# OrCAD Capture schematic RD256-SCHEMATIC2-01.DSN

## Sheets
1 10: size A3
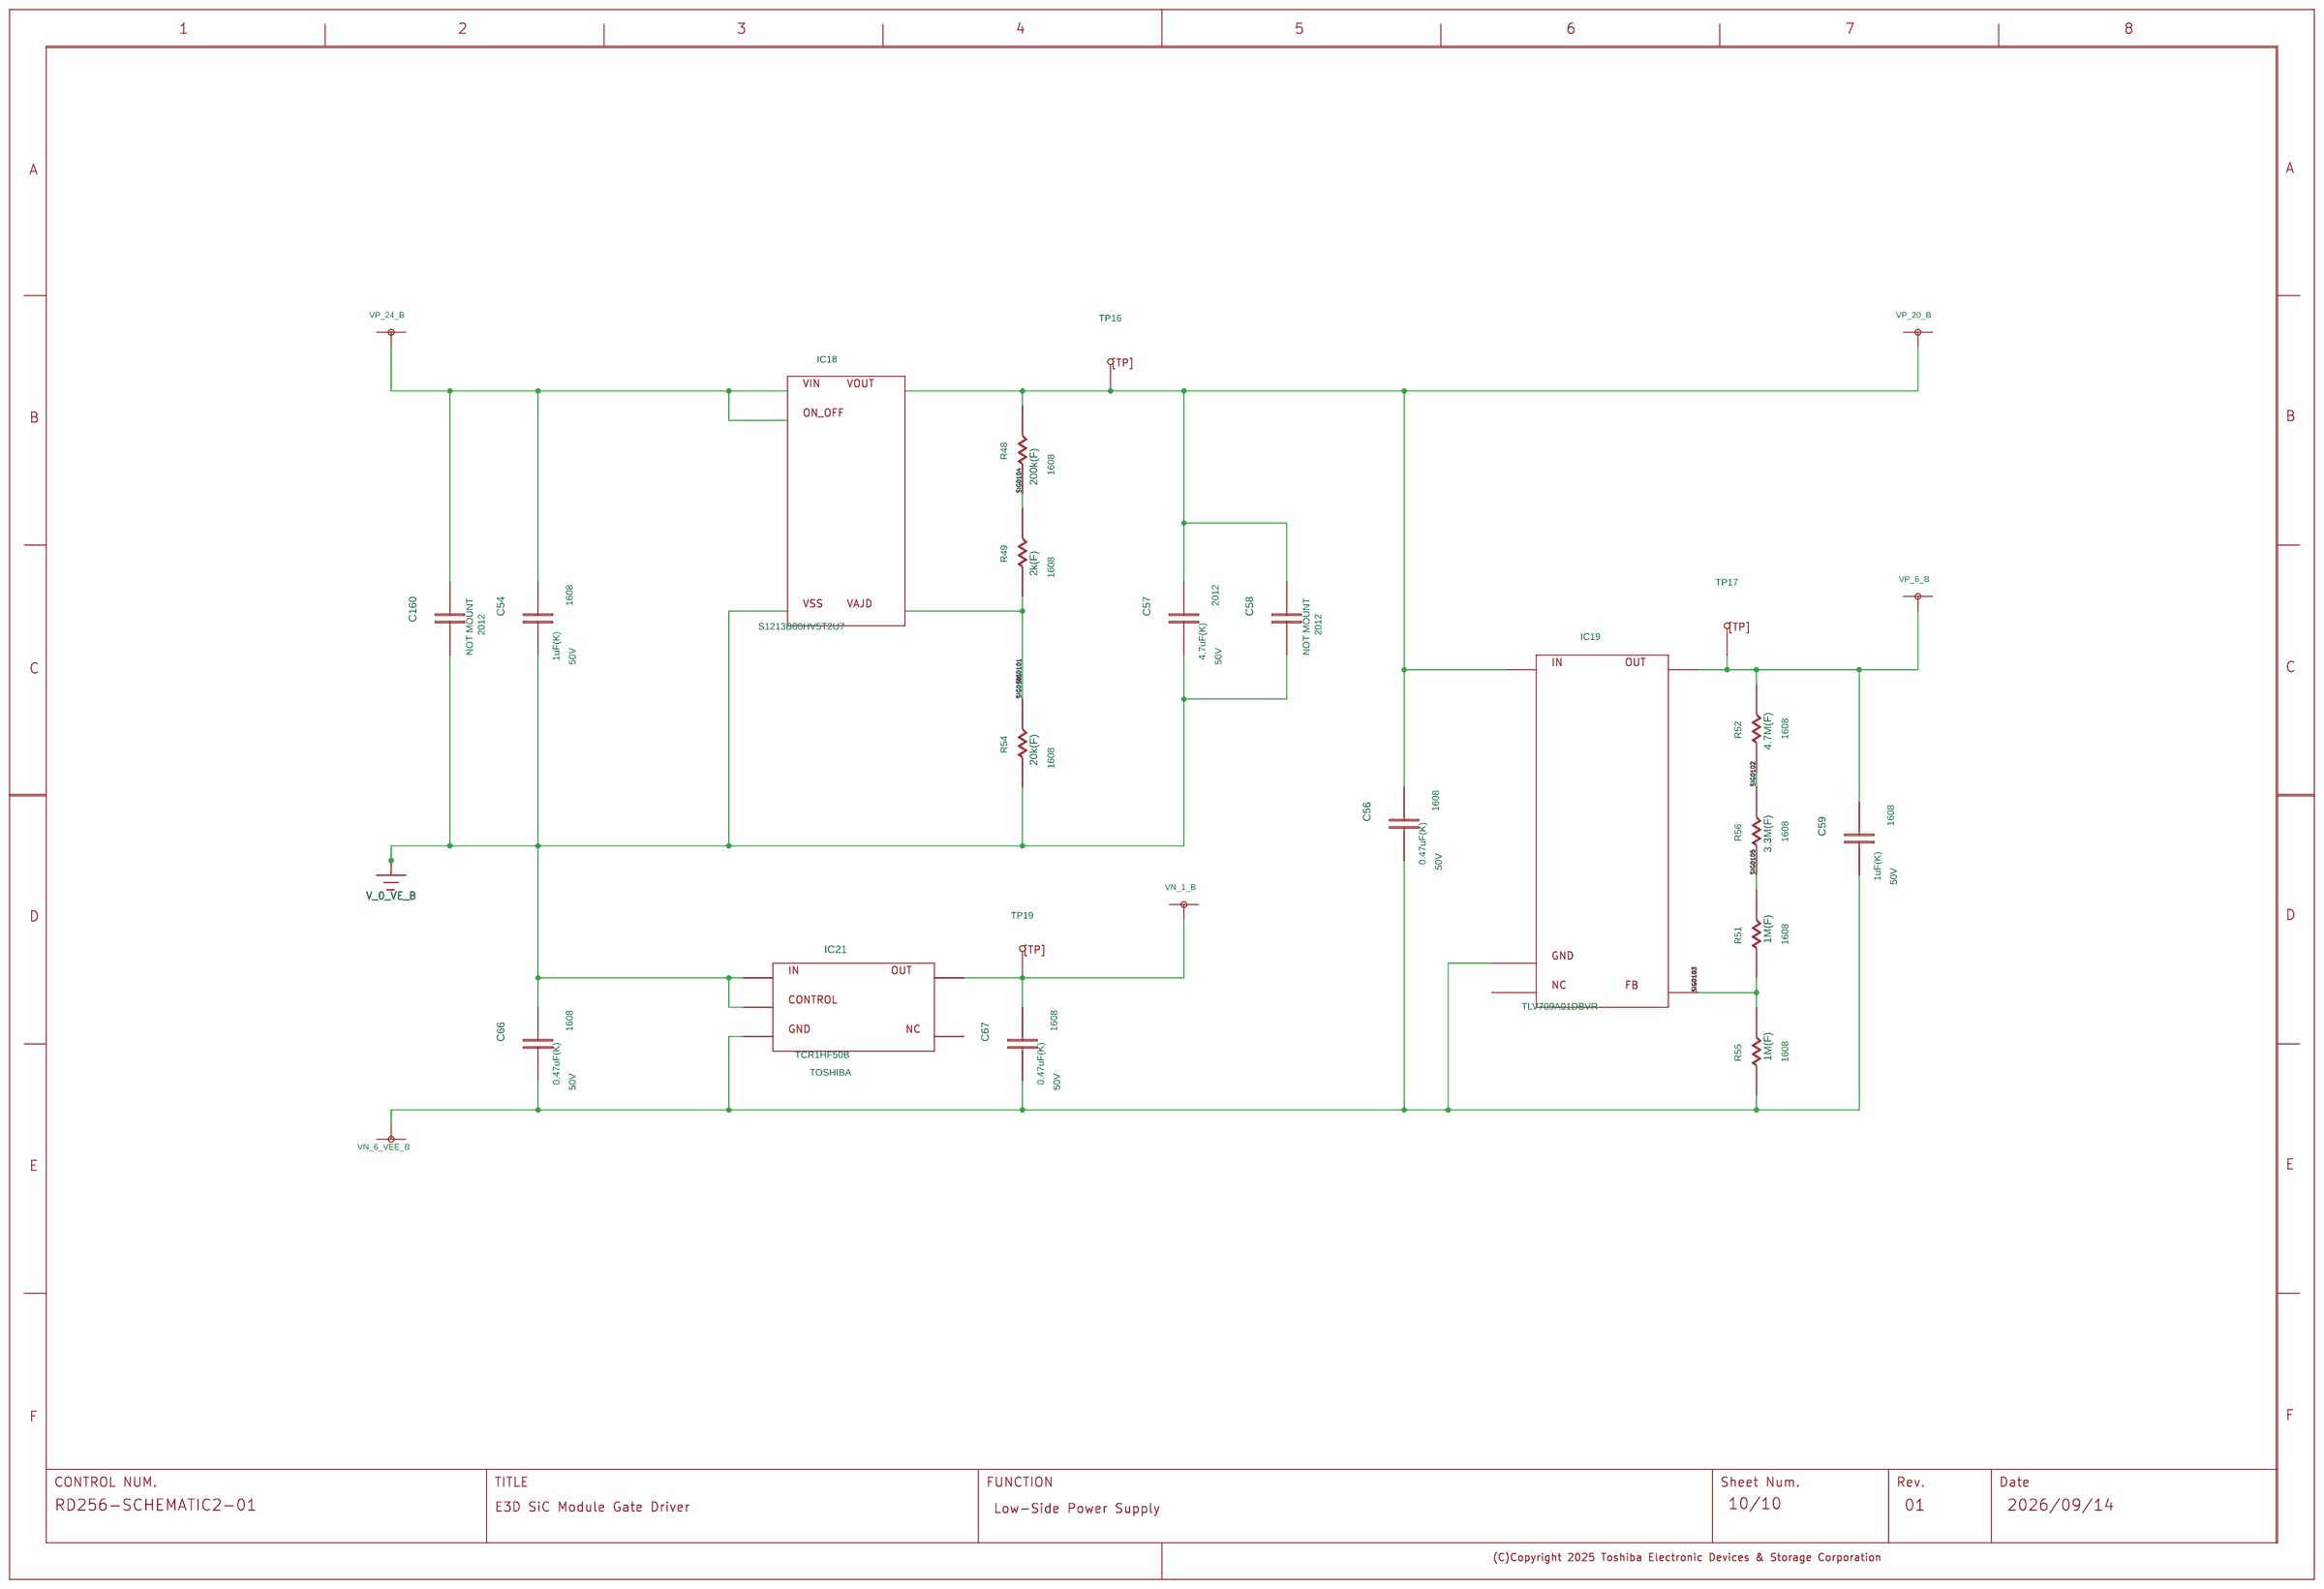
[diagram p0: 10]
2 9: size A3
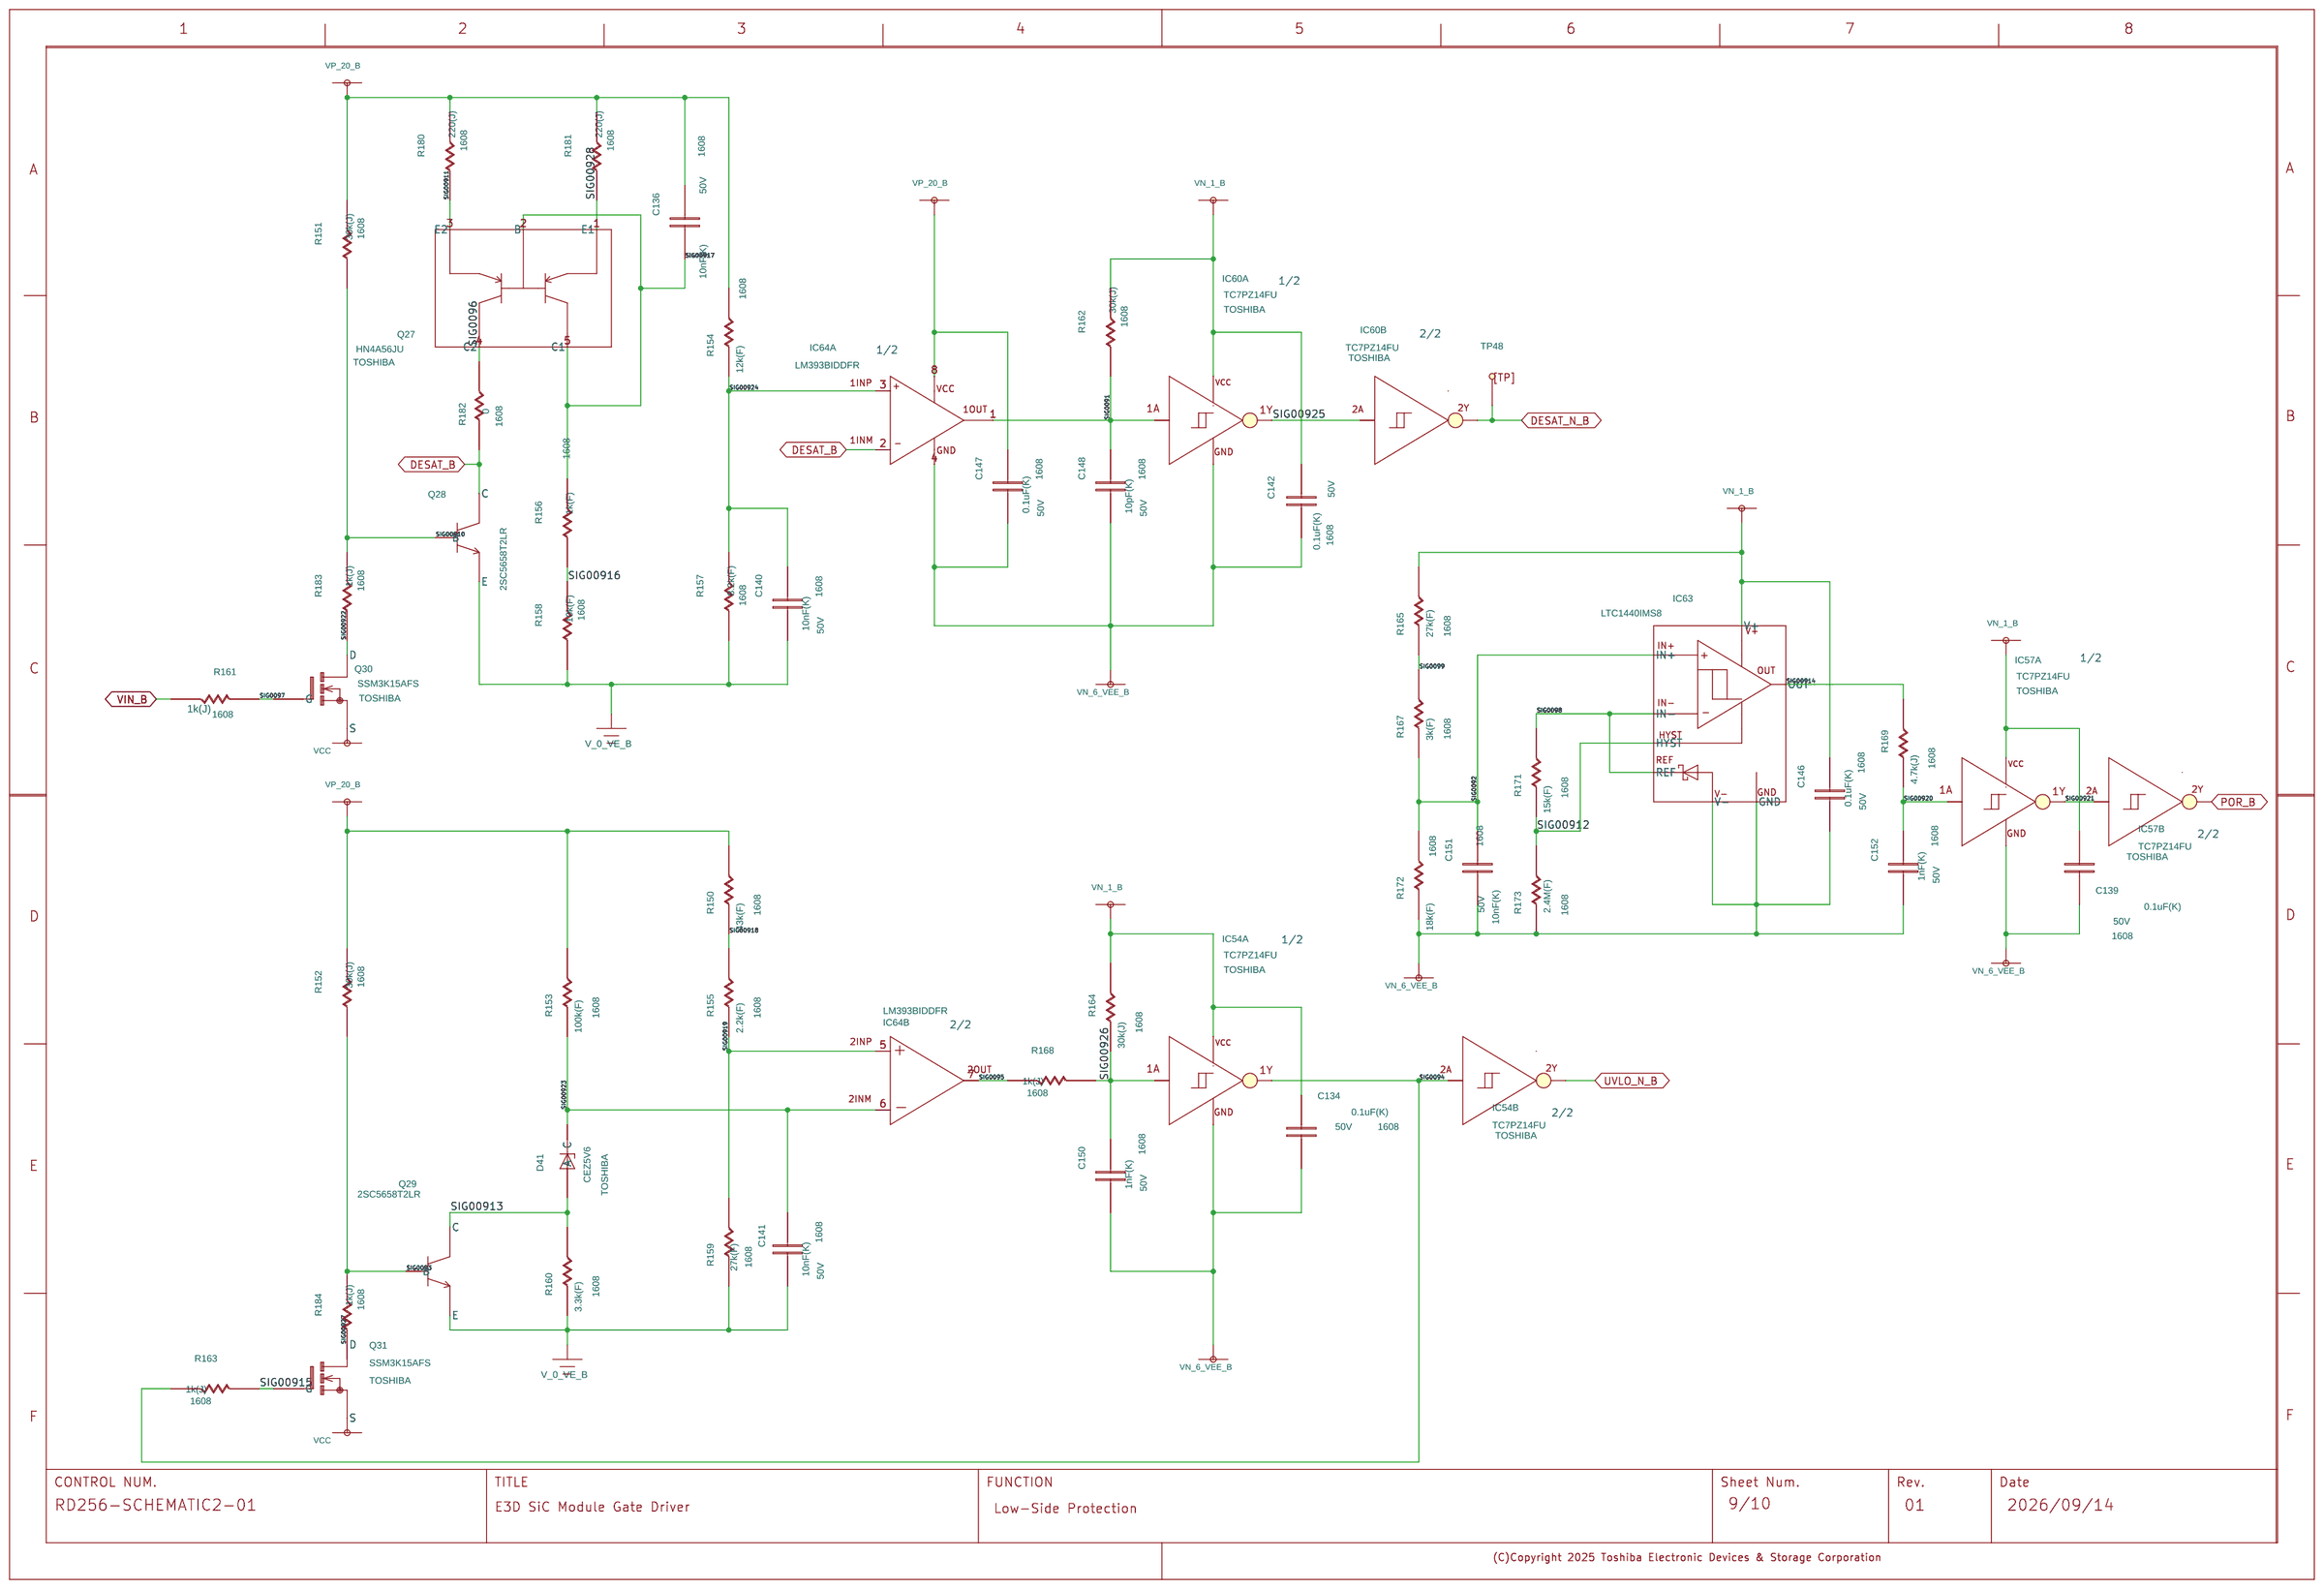
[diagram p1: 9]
3 8: size A3
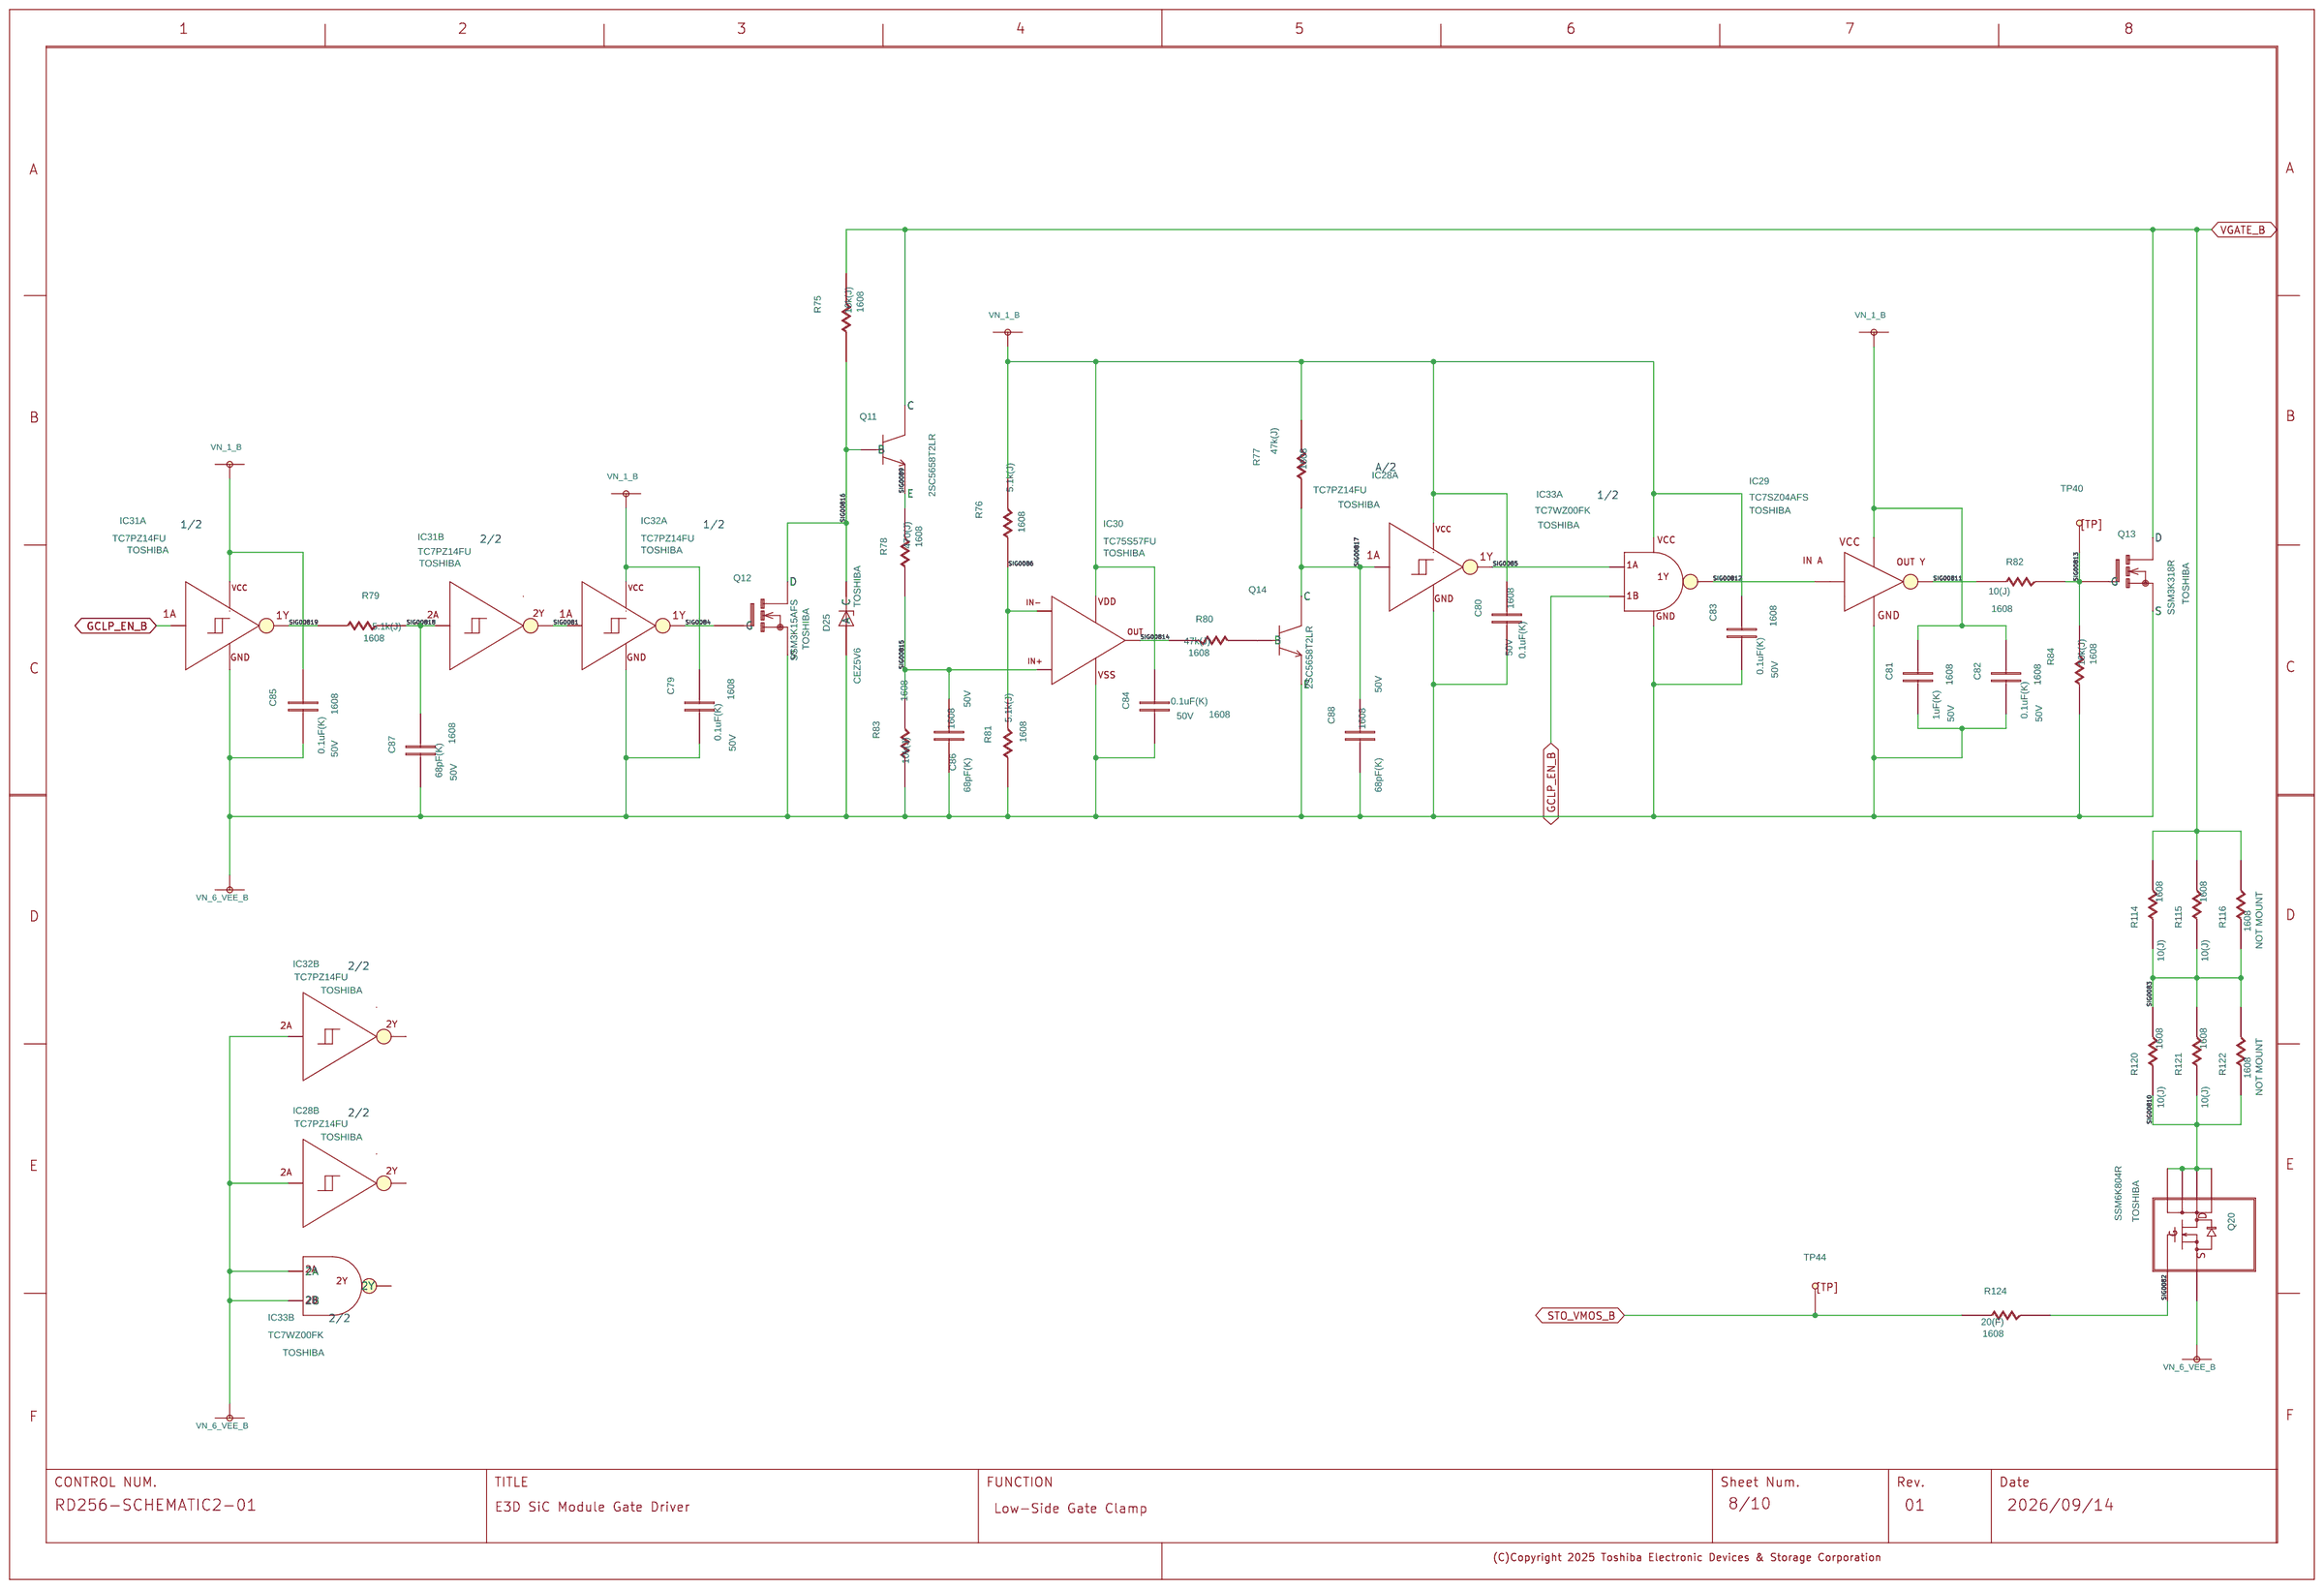
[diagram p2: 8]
4 7: size A3
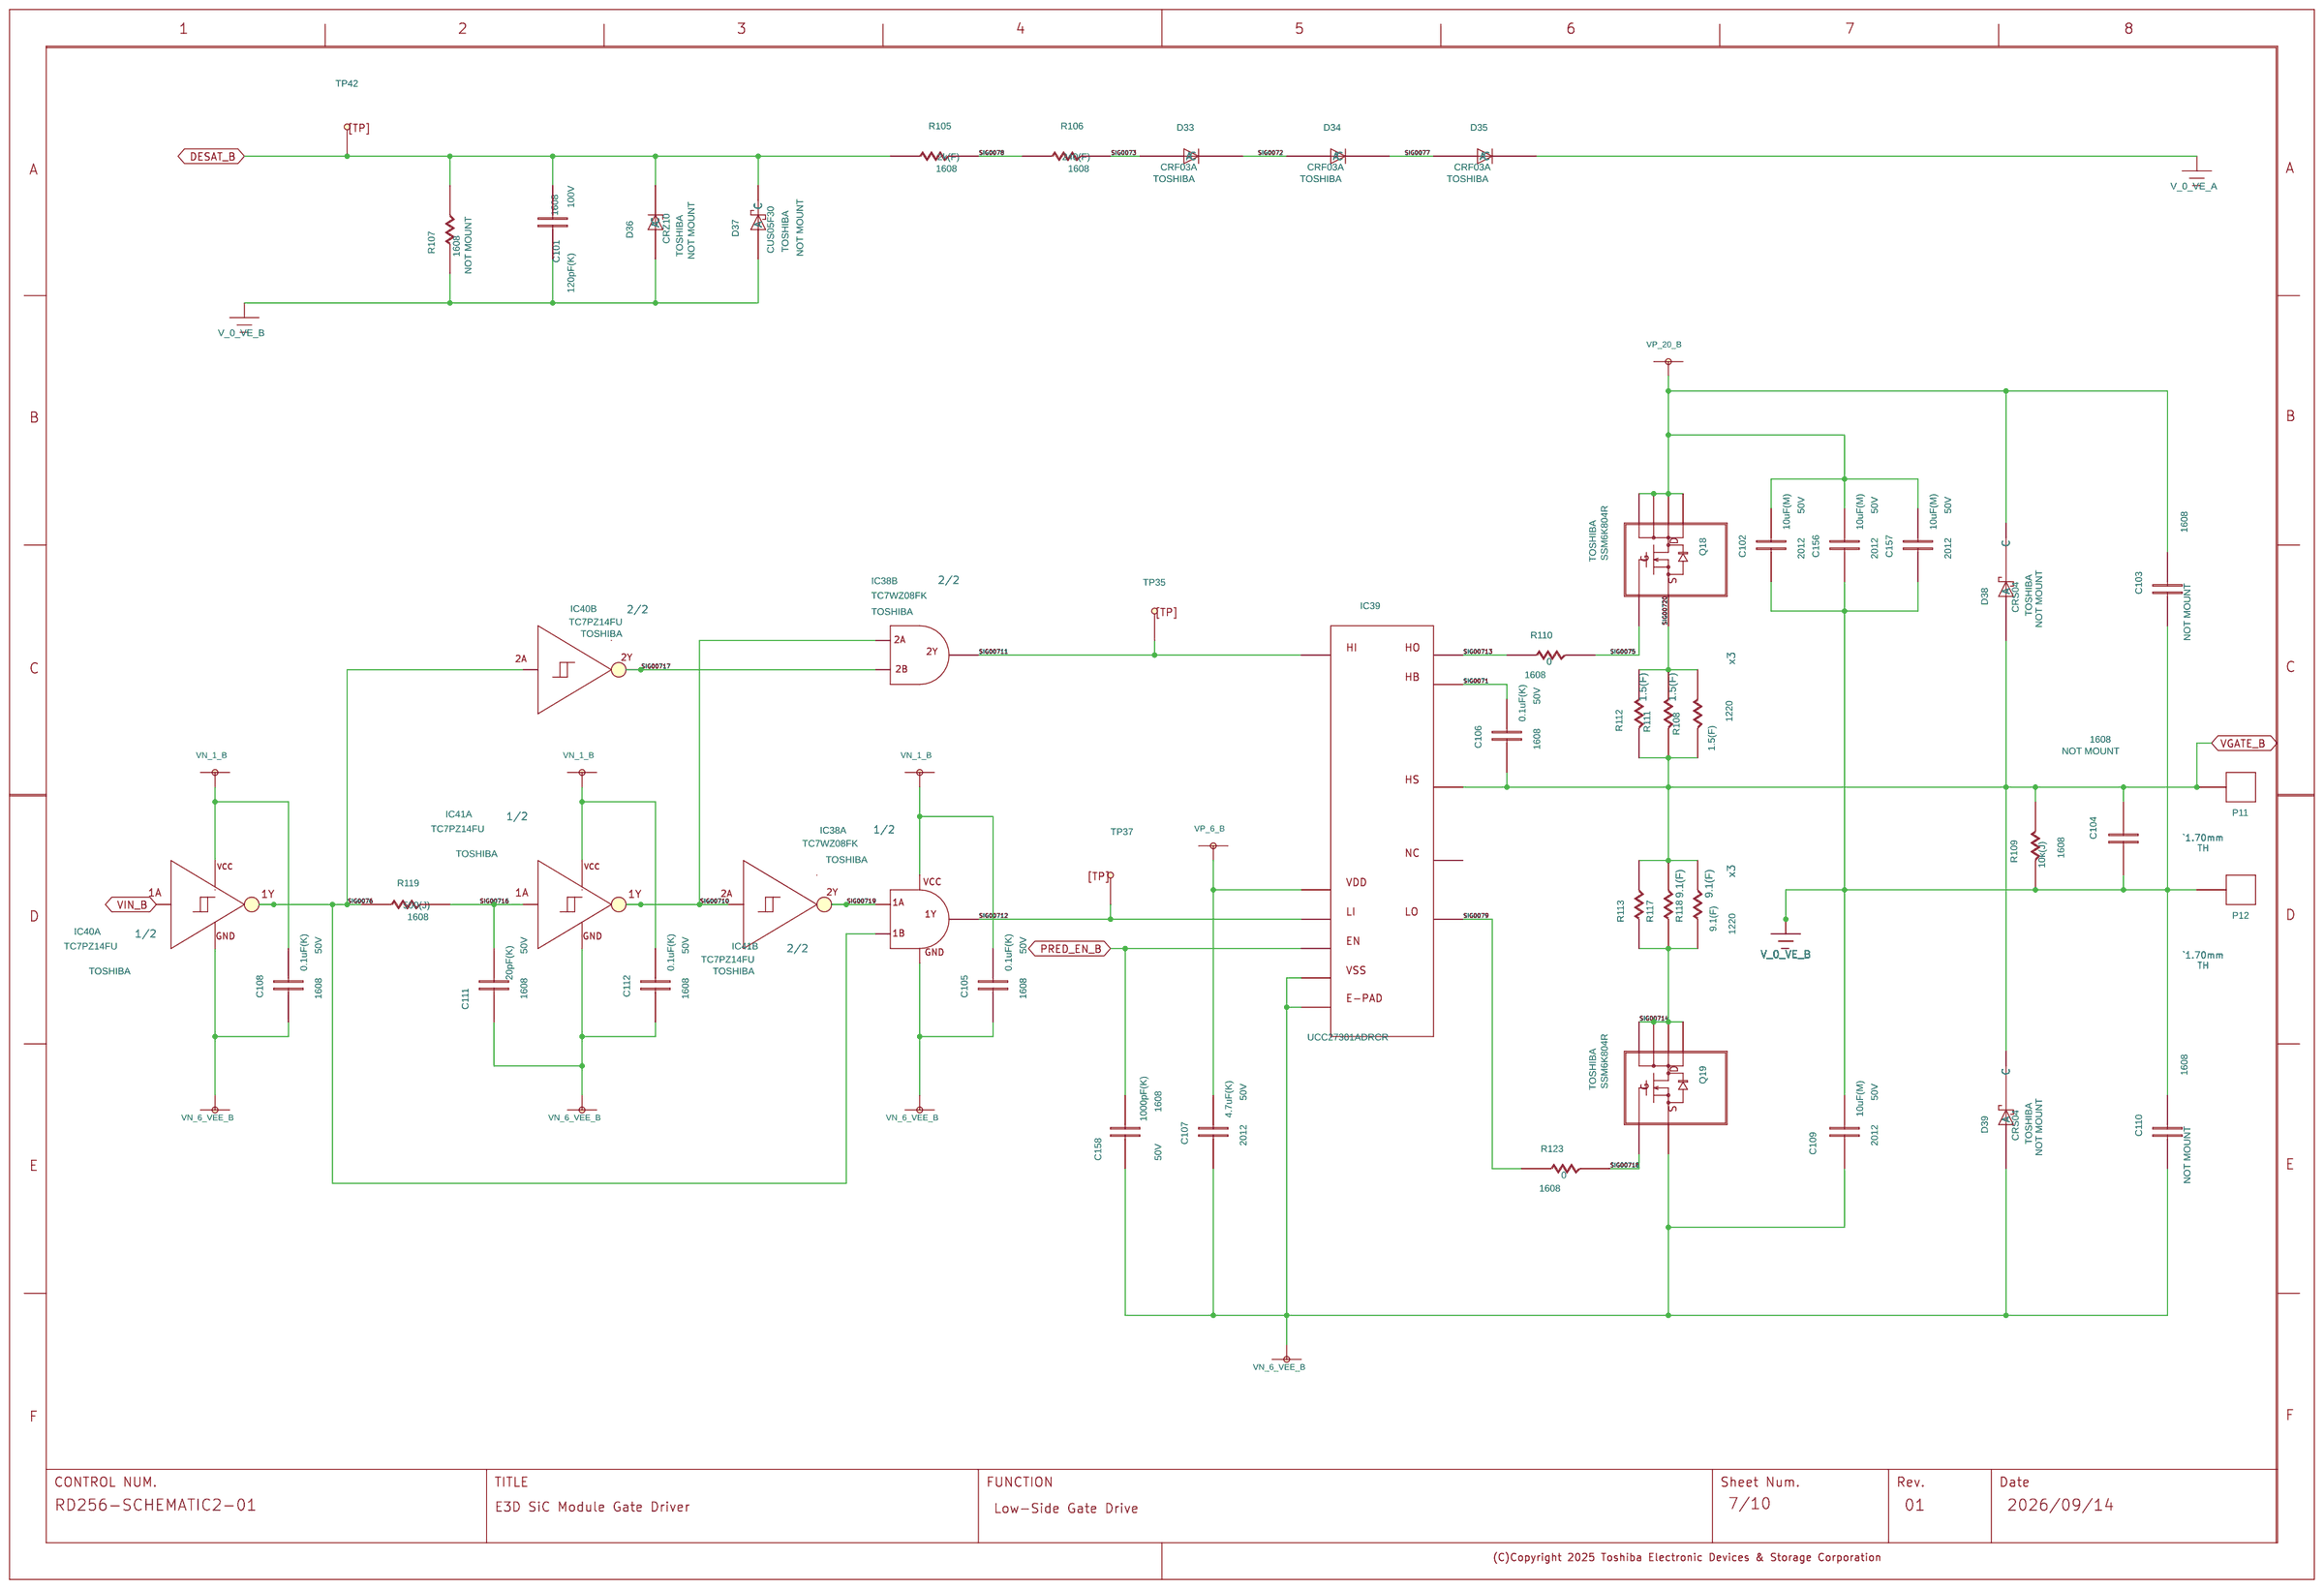
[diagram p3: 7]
5 6: size A3
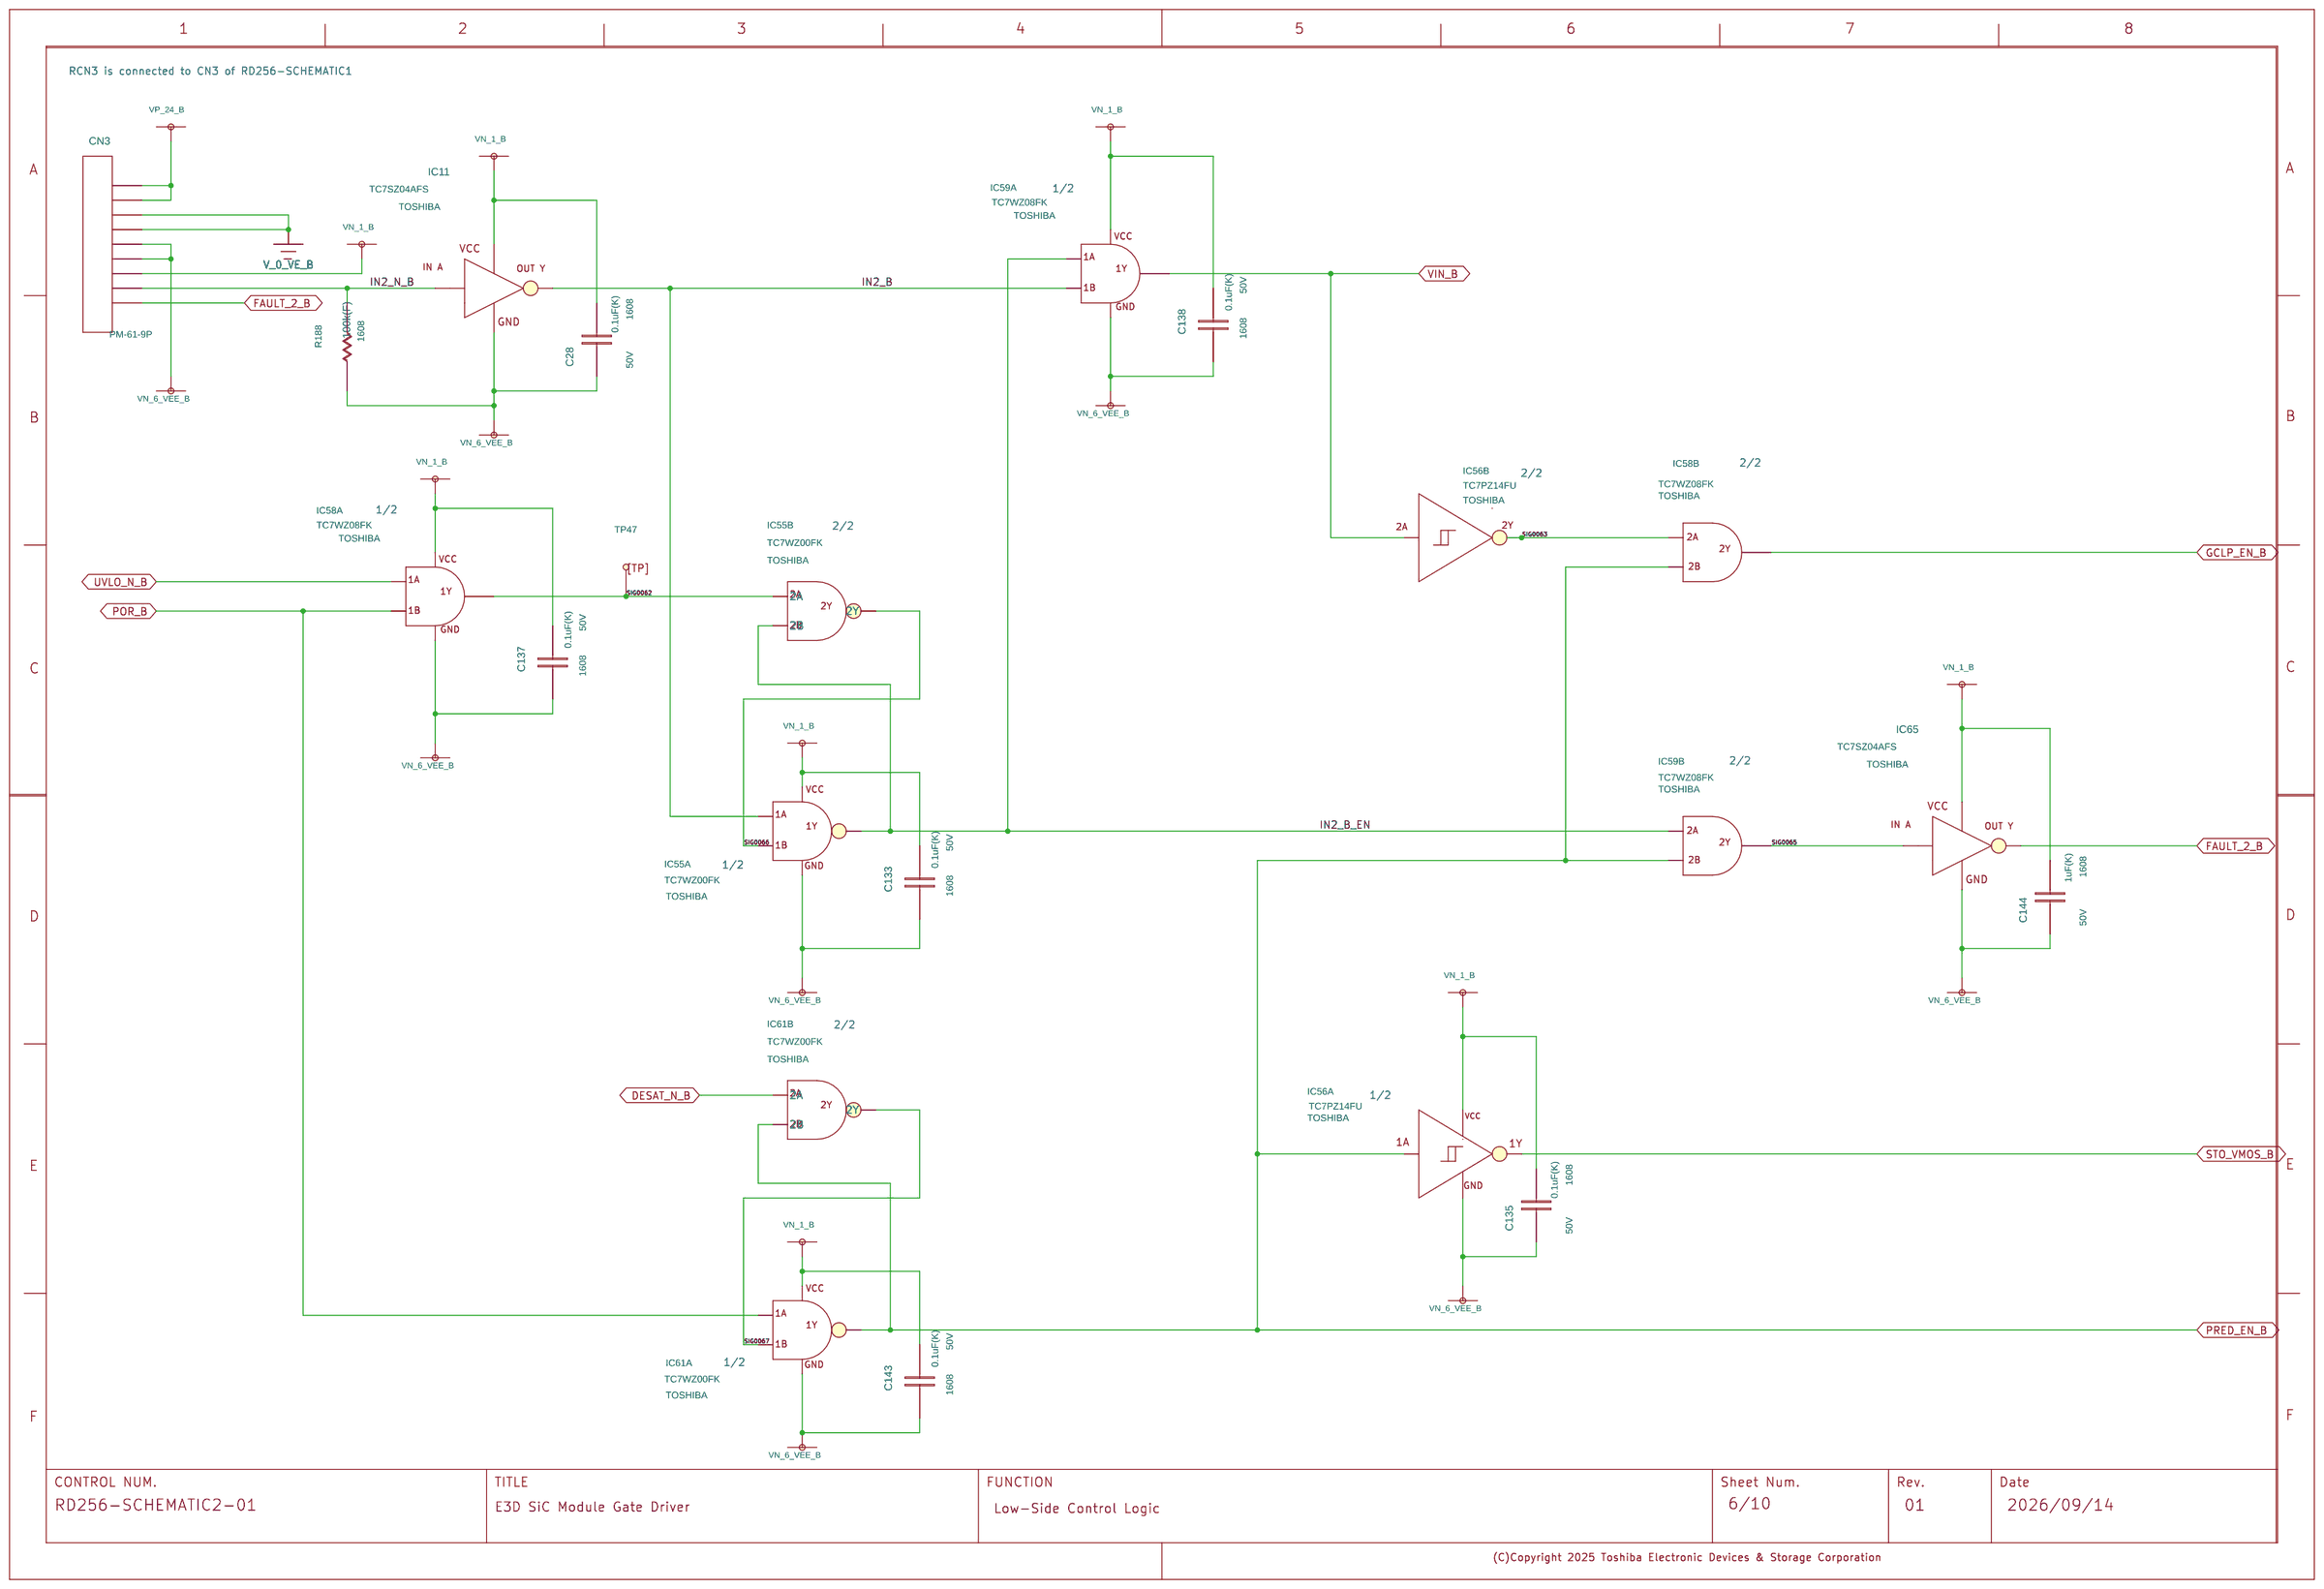
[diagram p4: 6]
6 5: size A3
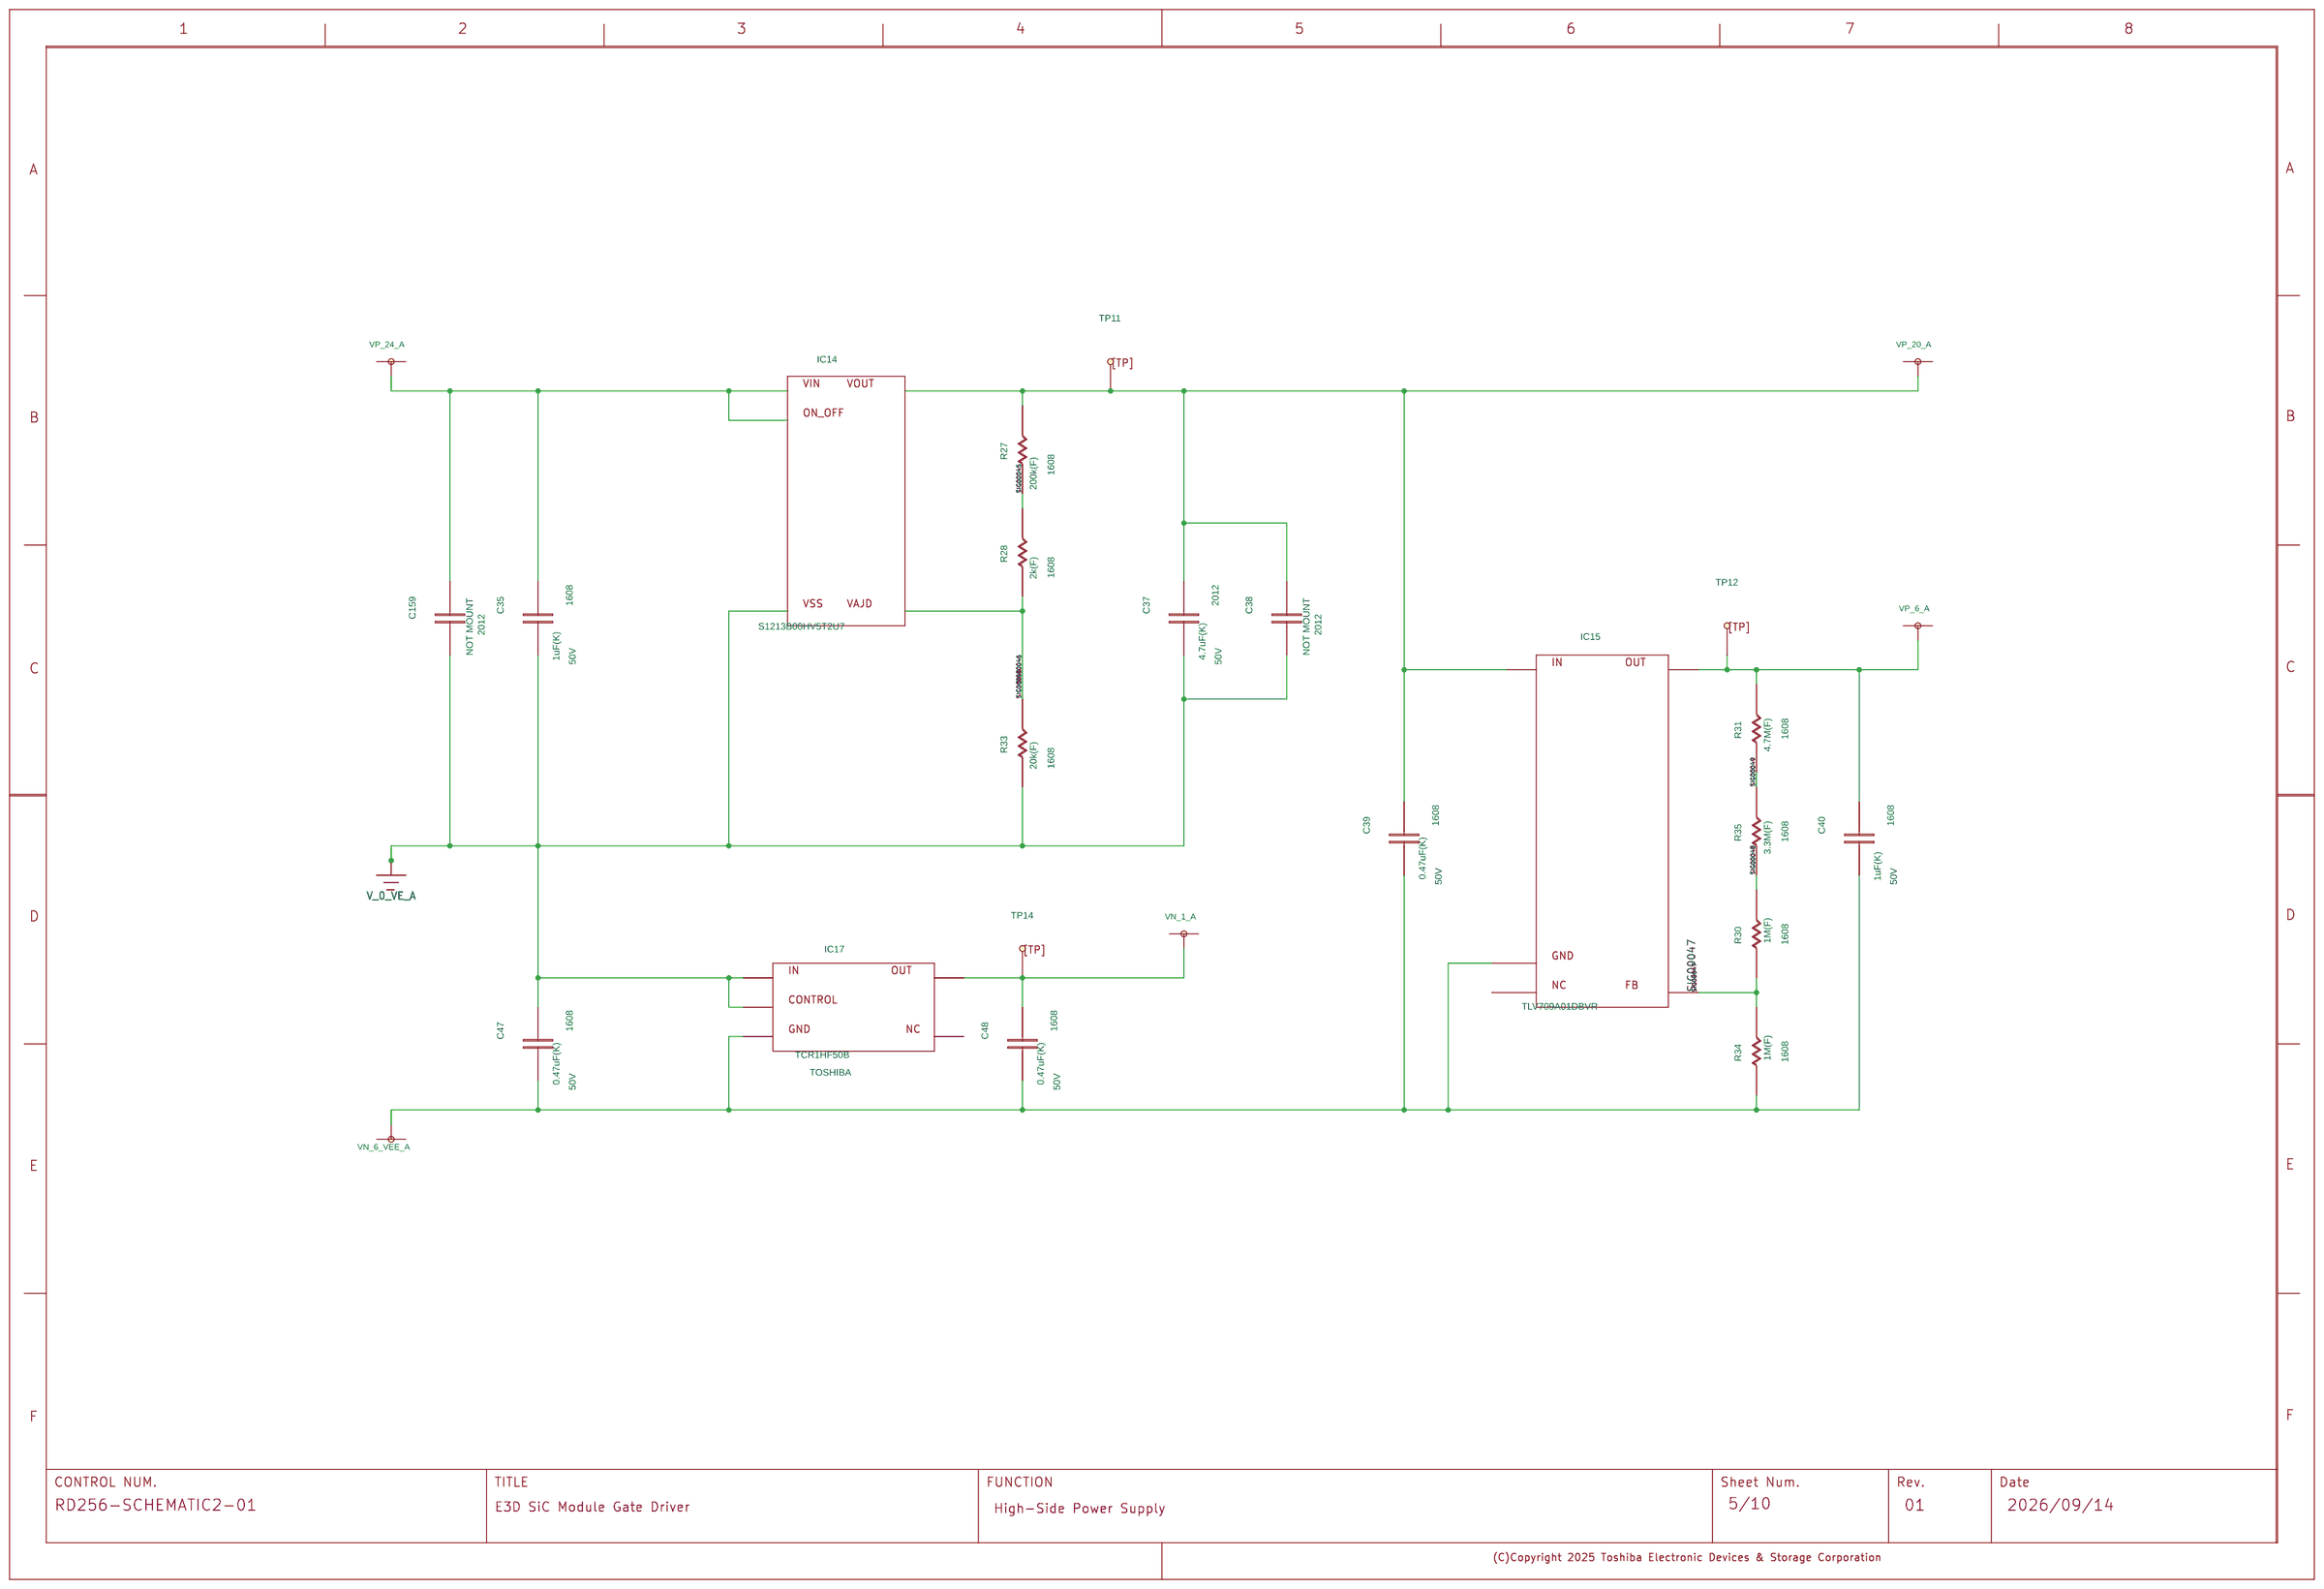
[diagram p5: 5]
7 4: size A3
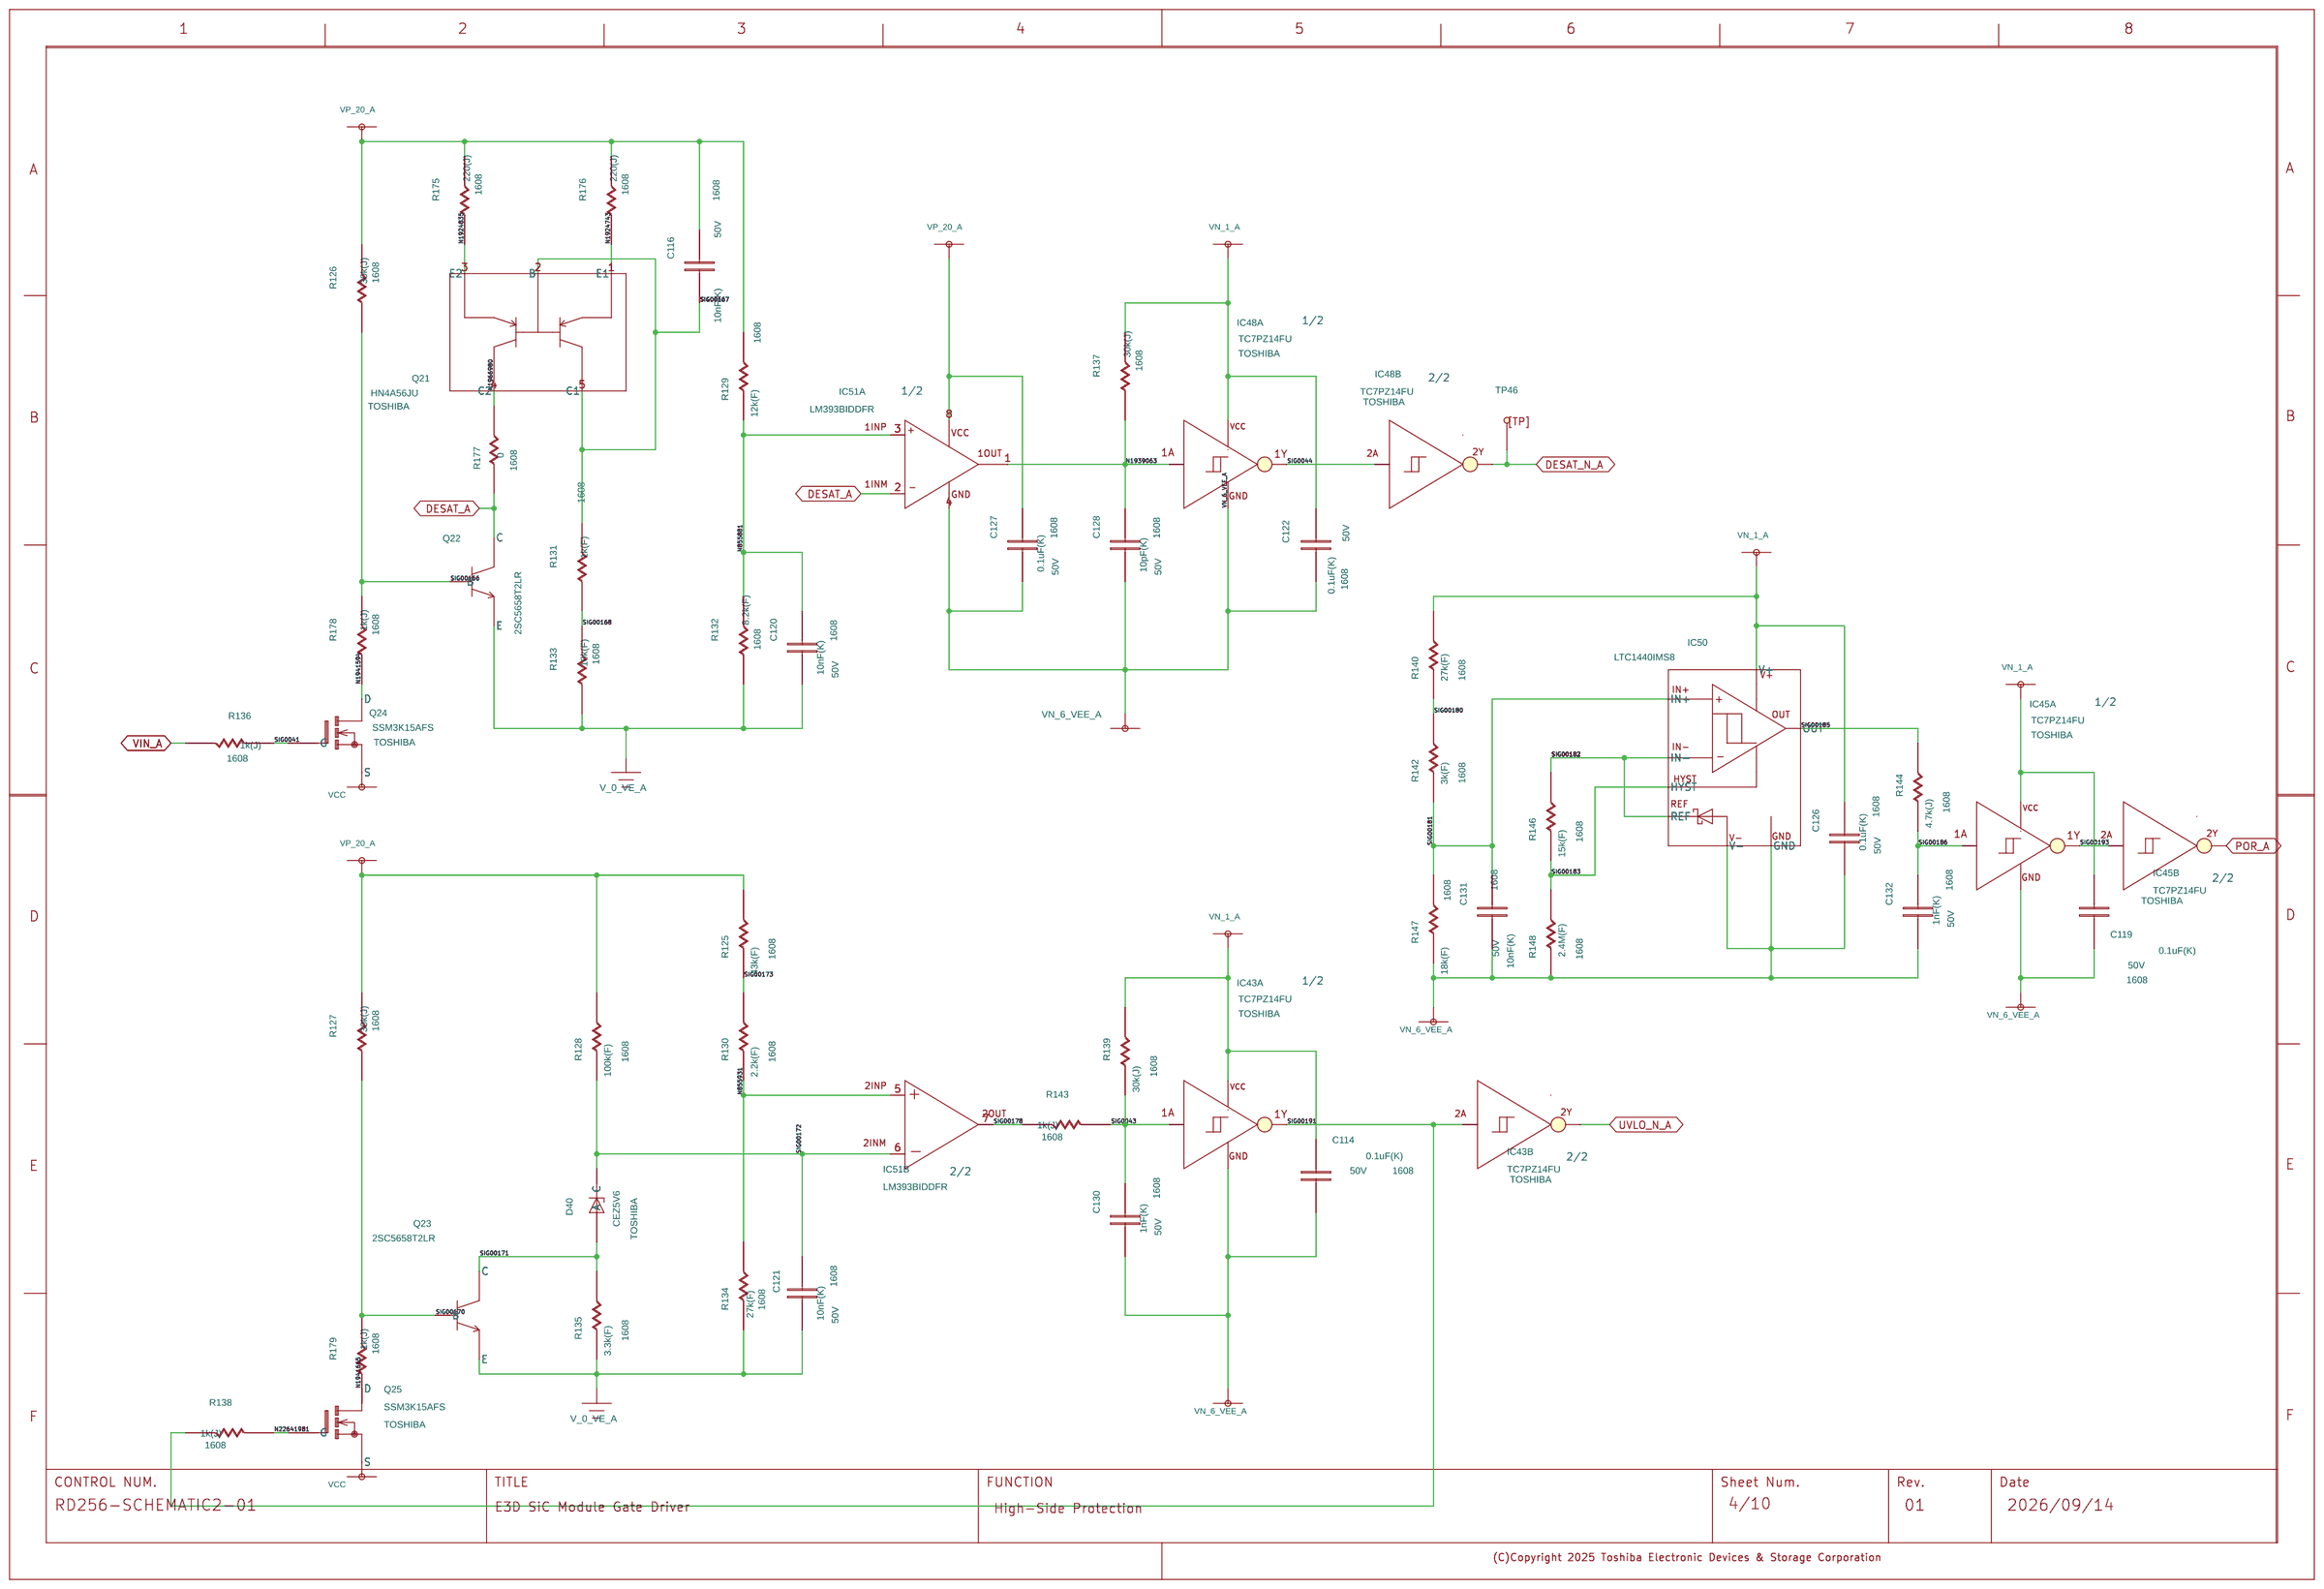
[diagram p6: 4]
8 3: size A3
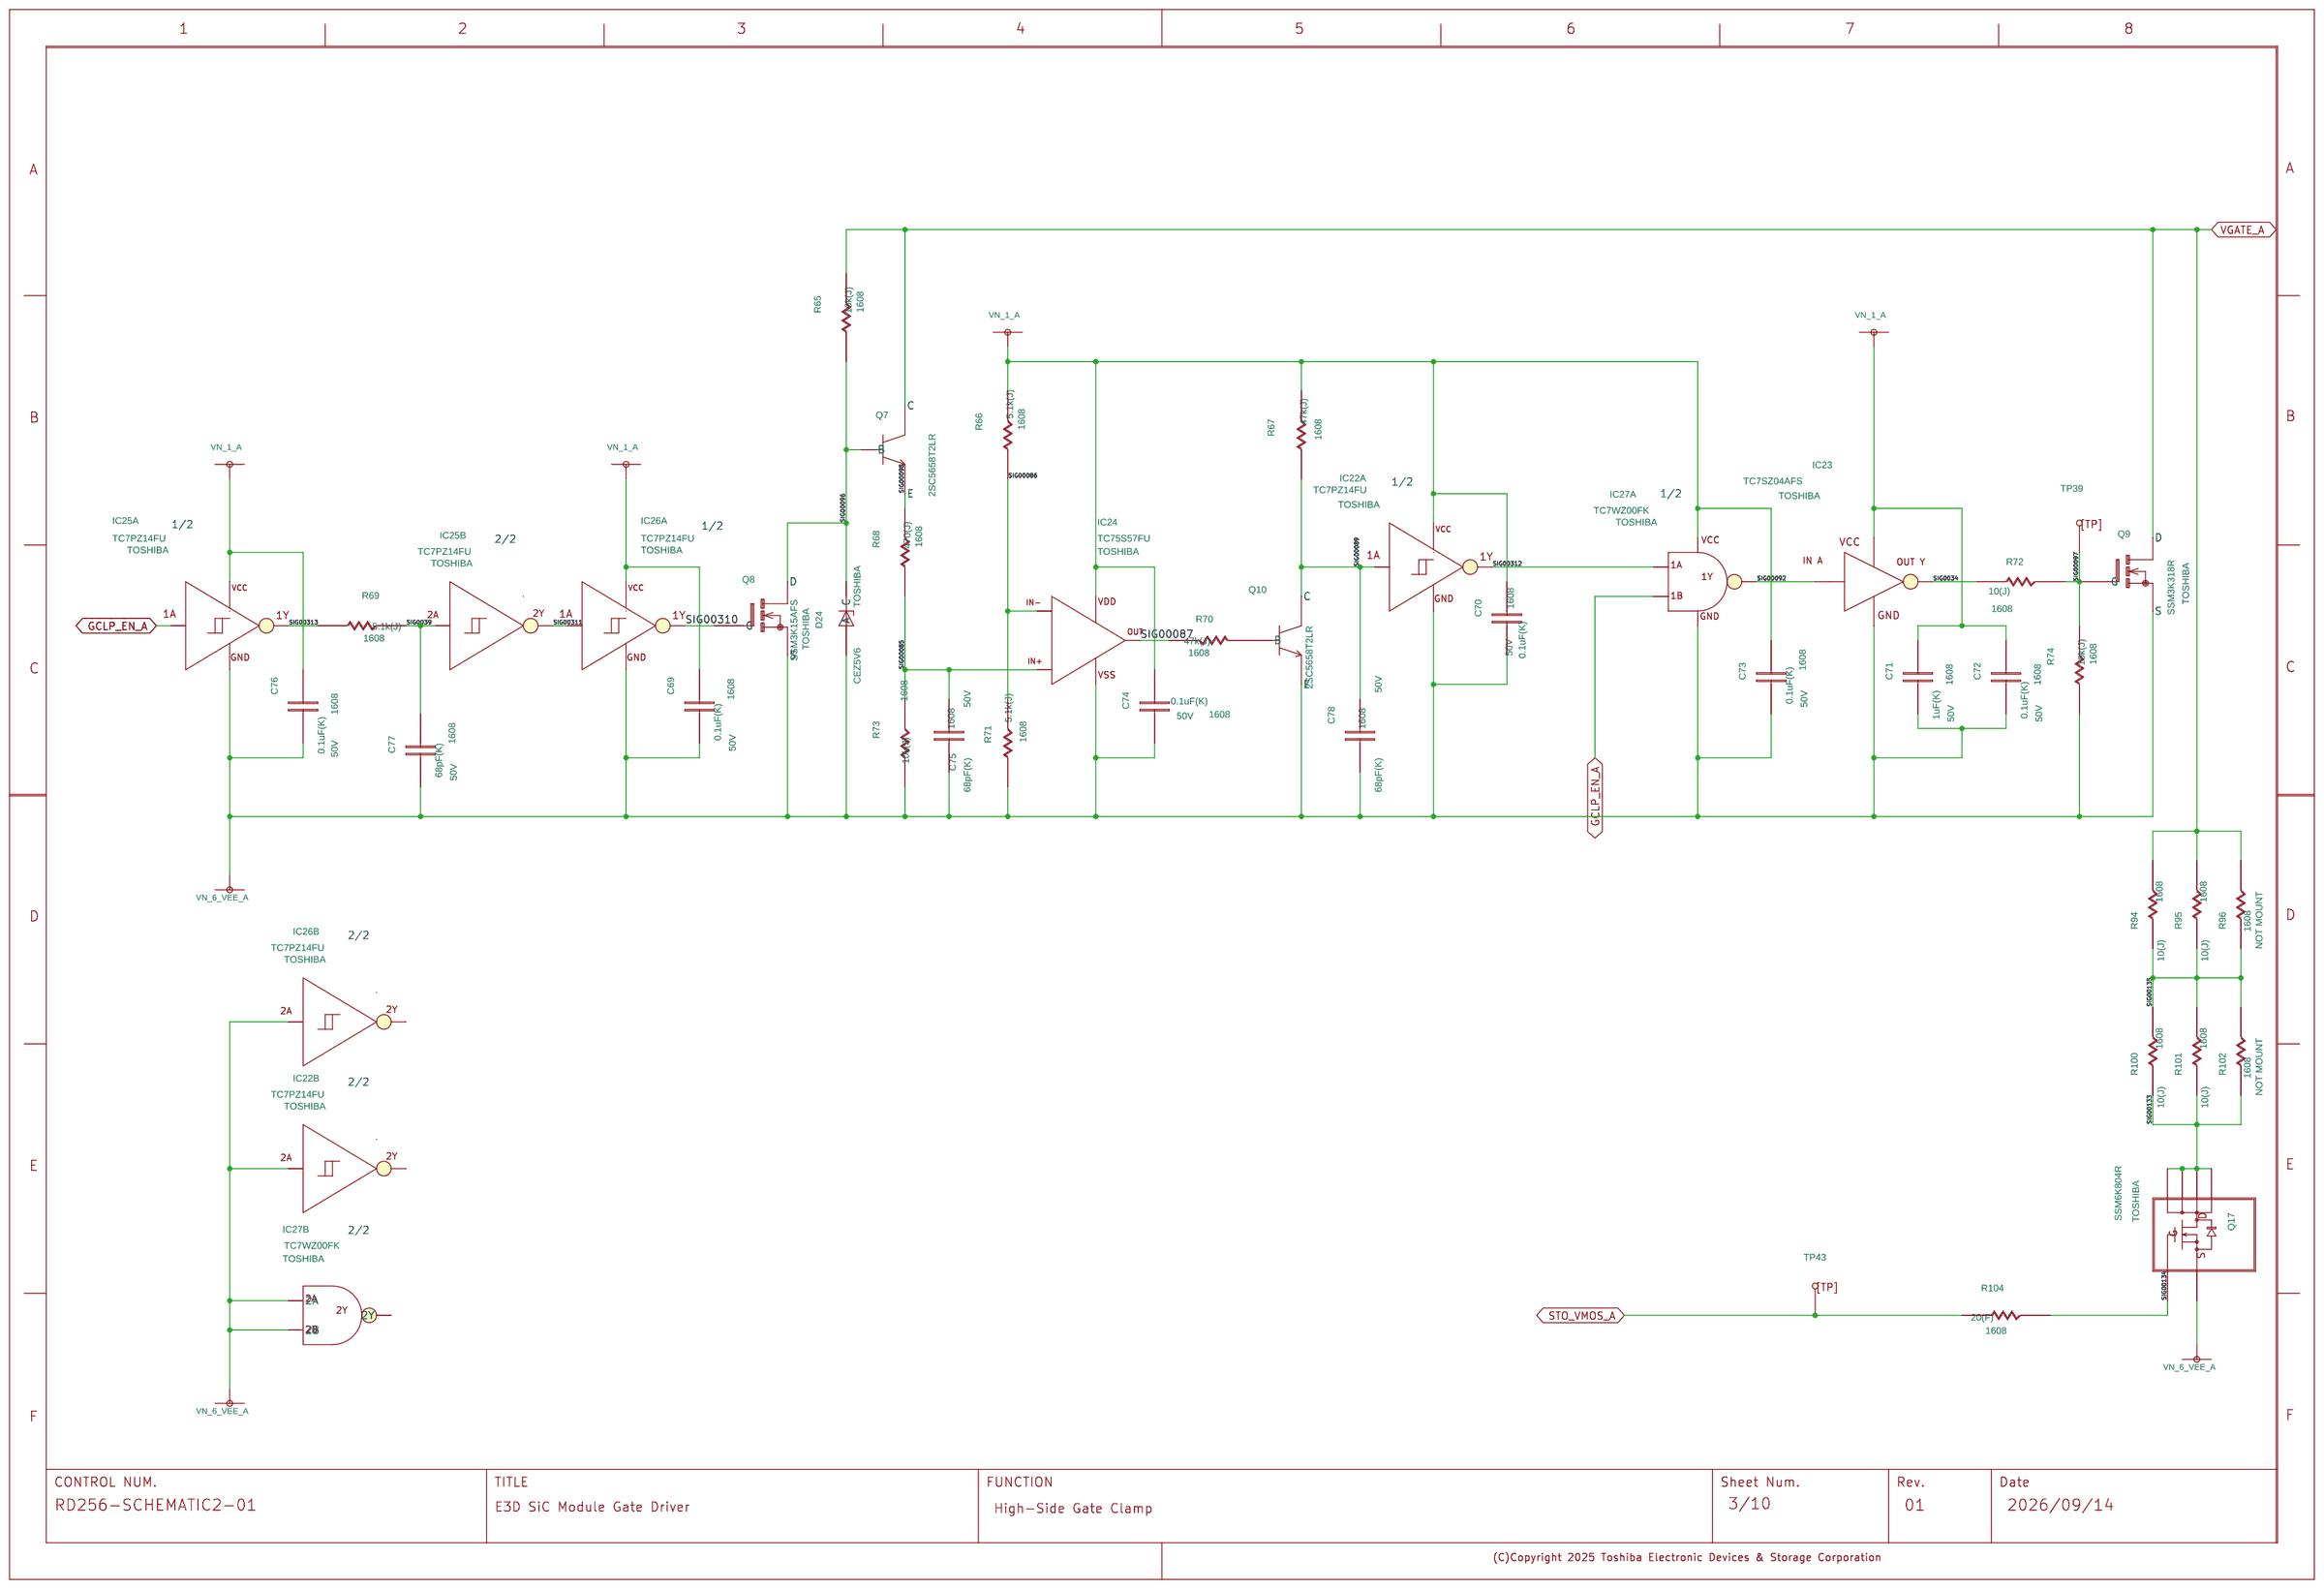
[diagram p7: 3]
9 2: size A3
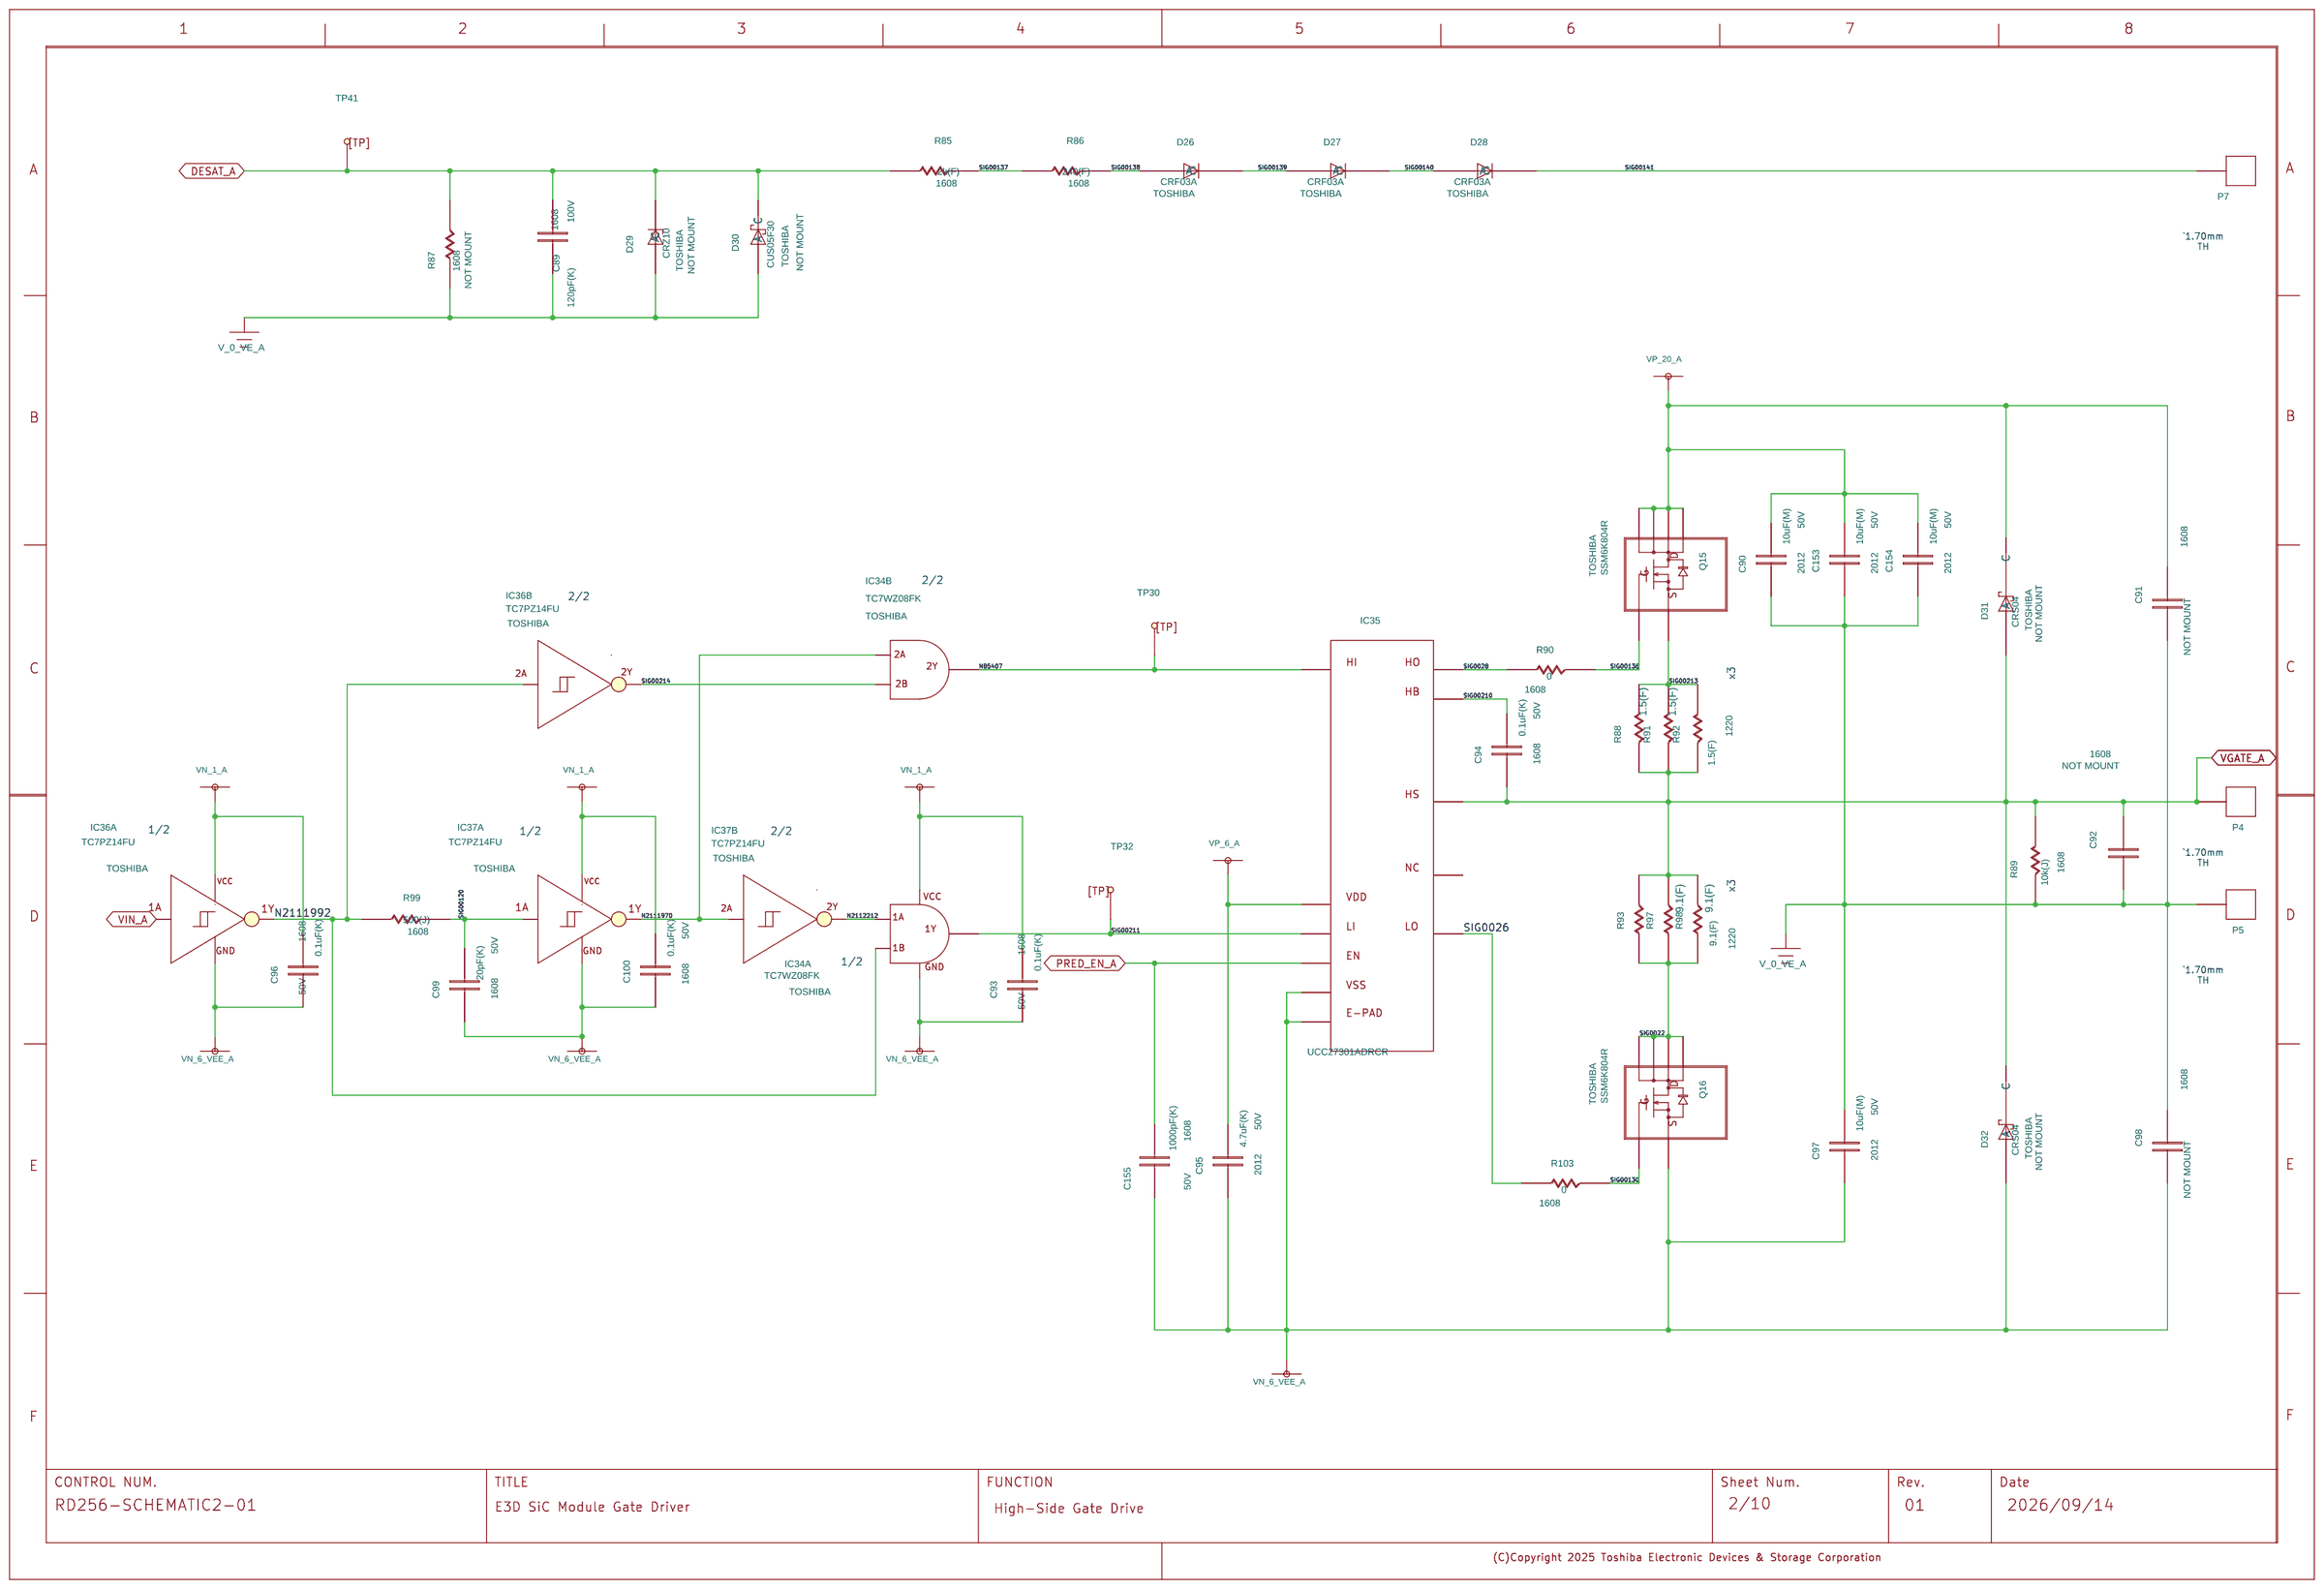
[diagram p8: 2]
10 1: size A3
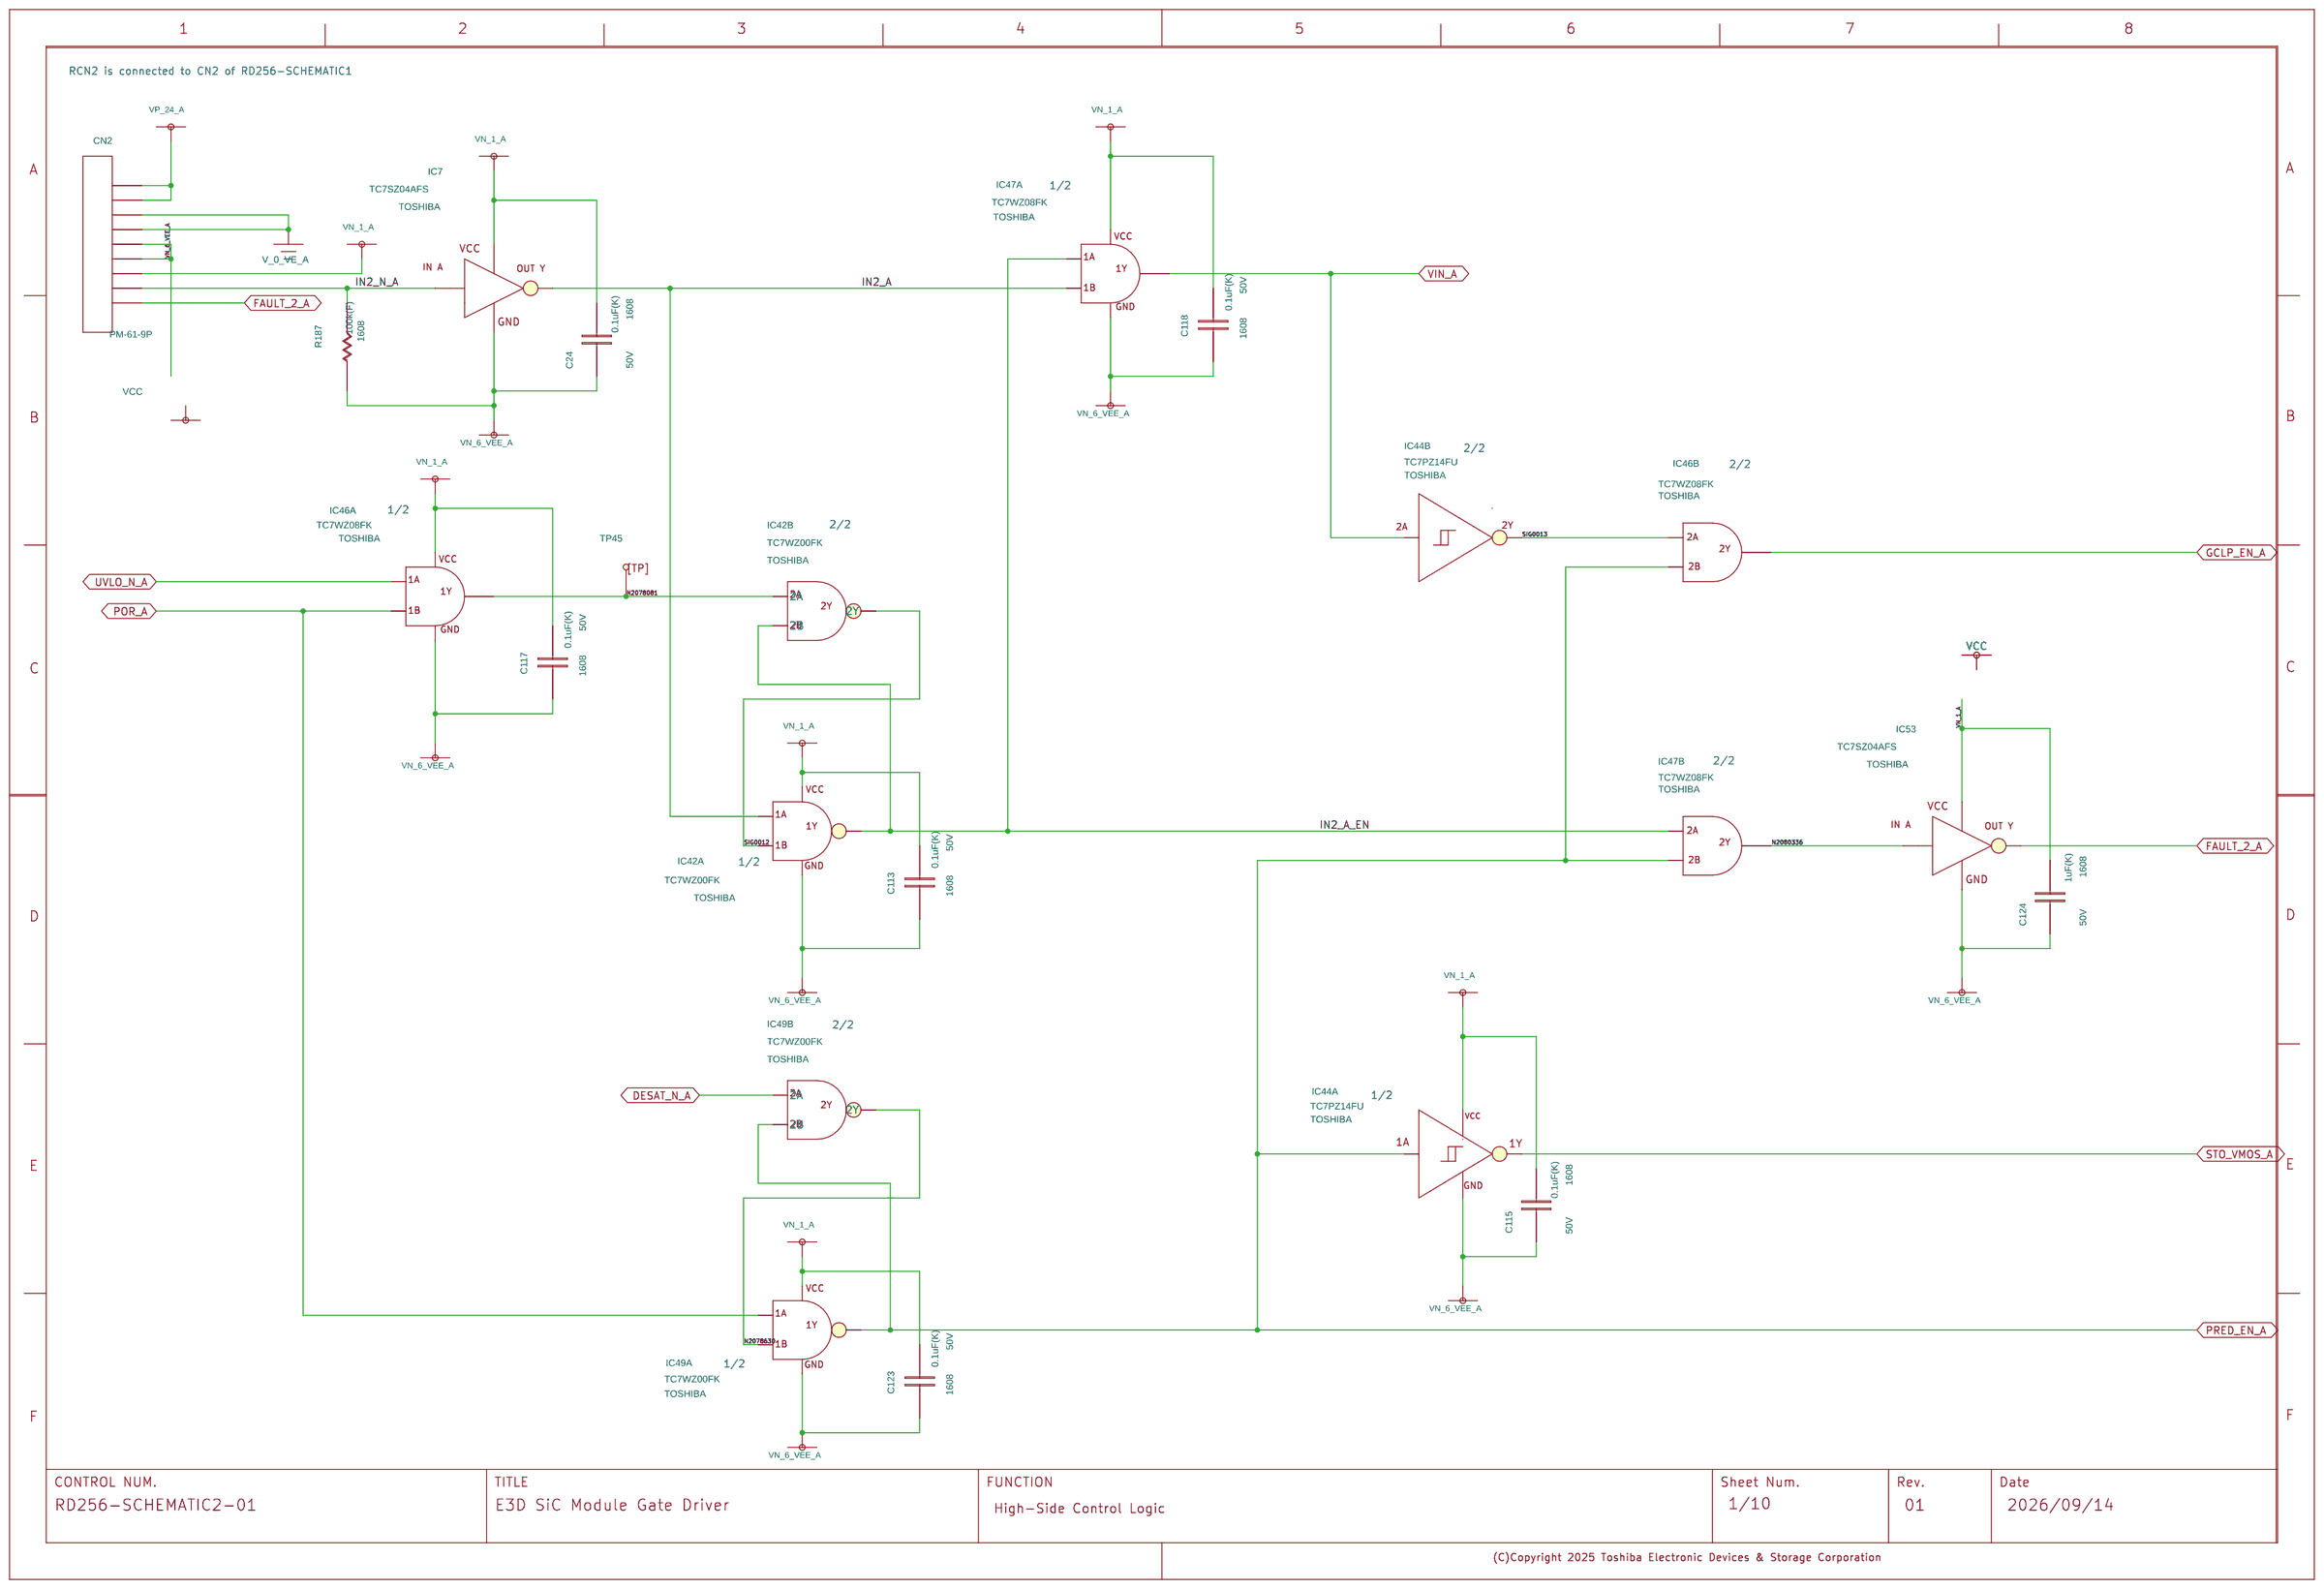
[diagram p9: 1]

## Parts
sheet 1
C24  C
C113  C
C115  C
C117  C
C118  C
C123  C
C124  C
CN2  CN9_2
IC7  TC7SZ04AFS
IC42  TC7WZ00FK  (sections A,B)
IC44  TC7PZ17FU  (sections A,B)
IC46  TC7WZ08FK  (sections A,B)
IC47  TC7WZ08FK  (sections A,B)
IC49  TC7WZ00FK  (sections A,B)
IC53  TC7SZ04AFS
R187  R
TP45  TP
U?#9  WAKU_DEF100
sheet 2
C89  C
C90  C
C91  C
C92  C
C93  C
C94  C
C95  C
C96  C
C97  C
C98  C
C99  C
C100  C
C153  C
C154  C
C155  C
D26  CRF03A
D27  CRF03A
D28  CRF03A
D29  CRZ10
D30  CUS05F30
D31  CRS04
D32  CRS04
IC34  TC7WZ08FK  (sections A,B)
IC35  UCC27301A
IC36  TC7PZ17FU  (sections A,B)
IC37  TC7PZ17FU  (sections A,B)
P4  TH
P5  TH
P7  TH
Q15  SSM6K804R
Q16  SSM6K804R
R85  R
R86  R
R87  R
R88  R
R89  R
R90  R
R91  R
R92  R
R93  R
R97  R
R98  R
R99  R
R103  R
TP30  TP
TP32  TP
TP41  TP
U?#8  WAKU_DEF100
sheet 3
C69  C
C70  C
C71  C
C72  C
C73  C
C74  C
C75  C
C76  C
C77  C
C78  C
D24  CEZ5V6
IC22  TC7PZ17FU  (sections A,B)
IC23  TC7SZ04AFS
IC24  TC75S57FU
IC25  TC7PZ17FU  (sections A,B)
IC26  TC7PZ17FU  (sections A,B)
IC27  TC7WZ00FK  (sections A,B)
Q7  2SC5658J
Q8  SSM3K15AFS
Q9  SSM3K318R
Q10  2SC5658J
Q17  SSM6K804R
R65  R
R66  R
R67  R
R68  R
R69  R
R70  R
R71  R
R72  R
R73  R
R74  R
R94  R
R95  R
R96  R
R100  R
R101  R
R102  R
R104  R
TP39  TP
TP43  TP
U?#7  WAKU_DEF100
sheet 4
C114  C
C116  C
C119  C
C120  C
C121  C
C122  C
C126  C
C127  C
C128  C
C130  C
C131  C
C132  C
D40  CEZ5V6
IC43  TC7PZ17FU  (sections A,B)
IC45  TC7PZ17FU  (sections A,B)
IC48  TC7PZ17FU  (sections A,B)
IC50  LTC1440IS8
IC51  LM393B_1  (sections A,B)
Q21  HN4A56JU
Q22  2SC5658J
Q23  2SC5658J
Q24  SSM3K15AFS
Q25  SSM3K15AFS
R125  R
R126  R
R127  R
R128  R
R129  R
R130  R
R131  R
R132  R
R133  R
R134  R
R135  R
R136  R
R137  R
R138  R
R139  R
R140  R
R142  R
R143  R
R144  R
R146  R
R147  R
R148  R
R175  R
R176  R
R177  R
R178  R
R179  R
TP46  TP
U?#6  WAKU_DEF100
sheet 5
C35  C
C37  C
C38  C
C39  C
C40  C
C47  C
C48  C
C159  C
IC14  S1213B00HV5T2U7
IC15  TLV709
IC17  TCR1HF50B
R27  R
R28  R
R30  R
R31  R
R33  R
R34  R
R35  R
TP11  TP
TP12  TP
TP14  TP
U?#5  WAKU_DEF100
sheet 6
C28  C
C133  C
C135  C
C137  C
C138  C
C143  C
C144  C
CN3  CN9_2
IC11  TC7SZ04AFS
IC55  TC7WZ00FK  (sections A,B)
IC56  TC7PZ17FU  (sections A,B)
IC58  TC7WZ08FK  (sections A,B)
IC59  TC7WZ08FK  (sections A,B)
IC61  TC7WZ00FK  (sections A,B)
IC65  TC7SZ04AFS
R188  R
TP47  TP
U?#4  WAKU_DEF100
sheet 7
C101  C
C102  C
C103  C
C104  C
C105  C
C106  C
C107  C
C108  C
C109  C
C110  C
C111  C
C112  C
C156  C
C157  C
C158  C
D33  CRF03A
D34  CRF03A
D35  CRF03A
D36  CRZ10
D37  CUS05F30
D38  CRS04
D39  CRS04
IC38  TC7WZ08FK  (sections A,B)
IC39  UCC27301A
IC40  TC7PZ17FU  (sections A,B)
IC41  TC7PZ17FU  (sections A,B)
P11  TH
P12  TH
Q18  SSM6K804R
Q19  SSM6K804R
R105  R
R106  R
R107  R
R108  R
R109  R
R110  R
R111  R
R112  R
R113  R
R117  R
R118  R
R119  R
R123  R
TP35  TP
TP37  TP
TP42  TP
U?#3  WAKU_DEF100
sheet 8
C79  C
C80  C
C81  C
C82  C
C83  C
C84  C
C85  C
C86  C
C87  C
C88  C
D25  CEZ5V6
IC28  TC7PZ17FU  (sections A,B)
IC29  TC7SZ04AFS
IC30  TC75S57FU
IC31  TC7PZ17FU  (sections A,B)
IC32  TC7PZ17FU  (sections A,B)
IC33  TC7WZ00FK  (sections A,B)
Q11  2SC5658J
Q12  SSM3K15AFS
Q13  SSM3K318R
Q14  2SC5658J
Q20  SSM6K804R
R75  R
R76  R
R77  R
R78  R
R79  R
R80  R
R81  R
R82  R
R83  R
R84  R
R114  R
R115  R
R116  R
R120  R
R121  R
R122  R
R124  R
TP40  TP
TP44  TP
U?#2  WAKU_DEF100
sheet 9
C134  C
C136  C
C139  C
C140  C
C141  C
C142  C
C146  C
C147  C
C148  C
C150  C
C151  C
C152  C
D41  CEZ5V6
IC54  TC7PZ17FU  (sections A,B)
IC57  TC7PZ17FU  (sections A,B)
IC60  TC7PZ17FU  (sections A,B)
IC63  LTC1440IS8
IC64  LM393B_1  (sections A,B)
Q27  HN4A56JU
Q28  2SC5658J
Q29  2SC5658J
Q30  SSM3K15AFS
Q31  SSM3K15AFS
R150  R
R151  R
R152  R
R153  R
R154  R
R155  R
R156  R
R157  R
R158  R
R159  R
R160  R
R161  R
R162  R
R163  R
R164  R
R165  R
R167  R
R168  R
R169  R
R171  R
R172  R
R173  R
R180  R
R181  R
R182  R
R183  R
R184  R
TP48  TP
U?#1  WAKU_DEF100
sheet 10
C54  C
C56  C
C57  C
C58  C
C59  C
C66  C
C67  C
C160  C
IC18  S1213B00HV5T2U7
IC19  TLV709
IC21  TCR1HF50B
R48  R
R49  R
R51  R
R52  R
R54  R
R55  R
R56  R
TP16  TP
TP17  TP
TP19  TP
U?#10  WAKU_DEF100

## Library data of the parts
C24 C28 C69 C70 C72-C74 C76 C79 C80 C82-C85 C93 C94 C96 C100 C105 C106 C108 C112-C115 C117-C119 C122 C123 C126 C127 C133-C135 C137-C139 C142 C143 C146 C147 = C: COMPONENTTYPE: 4; INSTANCENAME: INS2265204; SIZECODESMD: 1608; VAL1: 0.1uF(K); VAL2: 50V
C71 C81 C124 C144 = C: COMPONENTTYPE: 4; INSTANCENAME: INS2265204; SIZECODESMD: 1608; VAL1: 1uF(K); VAL2: 50V
CN2 CN3 = CN9_1: COMPONENTTYPE: 4; INSTANCENAME: INS2253568; VAL3: PM-61-9P
IC7 IC11 IC53 IC65 = TC7SZ04AFS: COMPONENTTYPE: 4; INSTANCENAME: INS2254048; USERCOMPTEXT3: TOSHIBA
IC42 IC49 IC55 IC61 = TC7WZ00FK_2: COMPONENTTYPE: 8; CaptureCellPackProp: TC7WZ00FK_2A; FUNCN: TC7WZ00FK_1; INSTANCENAME: INS2253652; SAVECOUNT: 5; USERCOMPTEXT3: TOSHIBA
IC43 IC44 IC48 IC54 IC57 IC60 = TC7PZ14FU_2: COMP: TC7PZ14FU; COMPONENTTYPE: 8; CaptureCellPackProp: TC7PZ14FU_2A; FUNCN: TC7PZ14FU_1; INSTANCENAME: INS2254016; USERCOMPTEXT3: TOSHIBA; VAL3: TC7PZ14FU
IC46 IC47 IC58 IC59 = TC7WZ08FK_1: COMPONENTTYPE: 8; CaptureCellPackProp: TC7WZ08FK_1A; INSTANCENAME: INS2254084; SAVECOUNT: 5; USERCOMPTEXT3: TOSHIBA
R128 R153 R187 R188 = R: COMPONENTTYPE: 4; INSTANCENAME: INS2263832; SIZECODESMD: 1608; VAL1: 100k(F); VAL2: 100mW
TP45 TP47 = TP: COMPONENTKIND: 127; COMPONENTTYPE: 4; INSTANCENAME: INS2253720
U?#9 = WAKU_DEF100: COMPONENTTYPE: 2; DATE: 2026/09/14; DRAWINGNUMBER: RD256-SCHEMATIC2-01; FUNCTION: High-Side Control Logic; REVISION: 01; SHEETNUMBER: 1/10; SHTSAVECOUNT: 35; TITLE: E3D SiC Module Gate Driver; UPDATEDATE: 2026.9.17; UPDATETIME: 12:22:00
C89 C101 = C: COMPONENTTYPE: 4; INSTANCENAME: INS2265204; SIZECODESMD: 1608; VAL1: 120pF(K); VAL2: 100V
C90 C97 C102 C109 C153 C154 C156 C157 = C: COMPONENTTYPE: 4; INSTANCENAME: INS2265204; SIZECODESMD: 2012; VAL1: 10uF(M); VAL2: 50V
C91 C92 C98 C103 C104 C110 = C: COMPONENTTYPE: 4; INSTANCENAME: INS2266227; NOTMOUNT: NOT MOUNT; SIZECODESMD: 1608
C95 C107 = C: COMPONENTTYPE: 4; INSTANCENAME: INS2265204; SIZECODESMD: 2012; VAL1: 4.7uF(K); VAL2: 50V
C99 C111 = C: COMPONENTTYPE: 4; INSTANCENAME: INS2265204; SIZECODESMD: 1608; VAL1: 20pF(K); VAL2: 50V
C155 C158 = C: COMPONENTTYPE: 4; INSTANCENAME: INS2265204; SIZECODESMD: 1608; VAL1: 1000pF(K); VAL2: 50V
D26-D28 D33-D35 = CRF03A: COMPONENTTYPE: 4; INSTANCENAME: INS2254974; USERCOMPTEXT3: TOSHIBA
D29 D36 = CRZ10: COMPONENTTYPE: 4; INSTANCENAME: INS2255026; NOTMOUNT: NOT MOUNT; USERCOMPTEXT3: TOSHIBA
D30 D37 = CUS05F30: COMPONENTTYPE: 4; INSTANCENAME: INS2255944; NOTMOUNT: NOT MOUNT; USERCOMPTEXT3: TOSHIBA
D31 D32 D38 D39 = CRS04: COMPONENTTYPE: 4; INSTANCENAME: INS2256112; NOTMOUNT: NOT MOUNT; USERCOMPTEXT3: TOSHIBA
IC34 = TC7WZ08FK_1: COMPONENTTYPE: 4; CaptureCellPackProp: TC7WZ08FK_1A; INSTANCENAME: INS2255192; USERCOMPTEXT3: TOSHIBA
IC35 IC39 = UCC27301A: COMPONENTTYPE: 4; VAL3: UCC27301ADRCR
IC36 = TC7PZ14FU_2: COMP: TC7PZ14FU; COMPONENTTYPE: 8; CaptureCellPackProp: TC7PZ14FU_2A; FUNCN: TC7PZ14FU_1; INSTANCENAME: INS2255542; USERCOMPTEXT3: TOSHIBA; VAL3: TC7PZ14FU
IC37 = TC7PZ14FU_2: COMP: TC7PZ14FU; COMPONENTTYPE: 8; CaptureCellPackProp: TC7PZ14FU_2B; INSTANCENAME: INS2255474; USERCOMPTEXT3: TOSHIBA; VAL3: TC7PZ14FU
P4 P11 = TH: COMPONENTTYPE: 4; INSTANCENAME: INS2255180
P5 P12 = TH: COMPONENTTYPE: 4; INSTANCENAME: INS2256066
P7 = TH: COMPONENTTYPE: 4; INSTANCENAME: INS2255754
Q15 Q16 Q18 Q19 = SSM6K804R: COMPONENTTYPE: 4; INSTANCENAME: INS2255292; USERCOMPTEXT3: TOSHIBA
R85 R105 = R: COMPONENTTYPE: 4; INSTANCENAME: INS2263832; SIZECODESMD: 1608; VAL1: 2k(F); VAL2: 100mW
R86 R106 = R: COMPONENTTYPE: 4; INSTANCENAME: INS2263832; SIZECODESMD: 1608; VAL1: 240(F); VAL2: 100mW
R87 R96 R102 R107 R116 R122 = R: COMPONENTTYPE: 4; INSTANCENAME: INS2263832; NOTMOUNT: NOT MOUNT; SIZECODESMD: 1608
R88 R91 R92 R108 R111 R112 = R: COMPONENTTYPE: 4; INSTANCENAME: INS2256002; SIZECODESMD: 1220; VAL1: 1.5(F); VAL2: 1W
R89 R109 = R: COMPONENTTYPE: 4; INSTANCENAME: INS2266059; SIZECODESMD: 1608; VAL1: 10k(J); VAL2: 100mW
R90 R103 R110 R123 = R: COMPONENTTYPE: 4; INSTANCENAME: INS2256002; SIZECODESMD: 1608; VAL1: 0
R93 R97 R98 R113 R117 R118 = R: COMPONENTTYPE: 4; INSTANCENAME: INS2256002; SIZECODESMD: 1220; VAL1: 9.1(F); VAL2: 1W
R99 R119 = R: COMPONENTTYPE: 4; INSTANCENAME: INS2263832; SIZECODESMD: 1608; VAL1: 500(J); VAL2: 100mW
TP30 TP35 = TP: COMPONENTKIND: 127; COMPONENTTYPE: 4; INSTANCENAME: INS2255892
TP32 TP37 = TP: COMPONENTKIND: 127; COMPONENTTYPE: 4; INSTANCENAME: INS2255530
TP41 TP42 = TP: COMPONENTKIND: 127; COMPONENTTYPE: 4; INSTANCENAME: INS2255794
U?#8 = WAKU_DEF100: COMPONENTTYPE: 2; DATE: 2026/09/14; DRAWINGNUMBER: RD256-SCHEMATIC2-01; FUNCTION: High-Side Gate Drive; REVISION: 01; SHEETNUMBER: 2/10; SHTSAVECOUNT: 39; TITLE: E3D SiC Module Gate Driver; UPDATEDATE: 2026.9.17; UPDATETIME: 12:22:00
C75 C77 C78 C86-C88 = C: COMPONENTTYPE: 4; INSTANCENAME: INS2265204; SIZECODESMD: 1608; VAL1: 68pF(K); VAL2: 50V
D24 D25 = CEZ5V6: COMPONENTTYPE: 4; INSTANCENAME: INS2262356; USERCOMPTEXT3: TOSHIBA
IC22 IC25 = TC7PZ14FU_2: COMP: TC7PZ14FU; COMPONENTTYPE: 8; CaptureCellPackProp: TC7PZ14FU_2A; FUNCN: TC7PZ14FU_1; USERCOMPTEXT3: TOSHIBA; VAL3: TC7PZ14FU
IC23 IC29 = TC7SZ04AFS: COMPONENTTYPE: 4; INSTANCENAME: INS2262788; USERCOMPTEXT3: TOSHIBA
IC24 = TC75S57FU: COMPONENTTYPE: 4; INSTANCENAME: INS2262824; SAVECOUNT: 2; USERCOMPTEXT3: TOSHIBA
IC26 IC31 = TC7PZ14FU_2: COMP: TC7PZ14FU; COMPONENTTYPE: 8; CaptureCellPackProp: TC7PZ14FU_2B; USERCOMPTEXT3: TOSHIBA; VAL3: TC7PZ14FU
IC27 = TC7WZ00FK_2: COMPONENTTYPE: 8; CaptureCellPackProp: TC7WZ00FK_2A; FUNCN: TC7WZ00FK_1; USERCOMPTEXT3: TOSHIBA
Q7 Q11 = 2SC5658J: COMPONENTTYPE: 4; INSTANCENAME: INS2262598; VAL3: 2SC5658T2LR
Q8 Q12 = SSM3K15AFS: COMPONENTTYPE: 4; INSTANCENAME: INS2262996; USERCOMPTEXT3: TOSHIBA
Q9 Q13 = SSM3K318R: COMPONENTTYPE: 4; INSTANCENAME: INS2261964; USERCOMPTEXT3: TOSHIBA
Q10 Q14 = 2SC5658J: COMPONENTTYPE: 4; INSTANCENAME: INS2262860; VAL3: 2SC5658T2LR
Q17 Q20 = SSM6K804R: COMPONENTTYPE: 4; INSTANCENAME: INS2262956; USERCOMPTEXT3: TOSHIBA
R65 R73-R75 R83 R84 = R: COMPONENTTYPE: 4; INSTANCENAME: INS2263832; SIZECODESMD: 1608; VAL1: 10k(J); VAL2: 100mW
R66 R69 R71 R76 R79 R81 = R: COMPONENTTYPE: 4; INSTANCENAME: INS2263832; SIZECODESMD: 1608; VAL1: 5.1k(J); VAL2: 100mW
R67 R70 R77 R80 = R: COMPONENTTYPE: 4; INSTANCENAME: INS2263832; SIZECODESMD: 1608; VAL1: 47k(J); VAL2: 100mW
R68 R78 = R: COMPONENTTYPE: 4; INSTANCENAME: INS2263832; SIZECODESMD: 1608; VAL1: 470(J); VAL2: 100mW
R72 R82 = R: COMPONENTTYPE: 4; INSTANCENAME: INS2262084; SIZECODESMD: 1608; VAL1: 10(J); VAL2: 100mW
R94 R95 R100 R101 R114 R115 R120 R121 = R: COMPONENTTYPE: 4; INSTANCENAME: INS2263832; SIZECODESMD: 1608; VAL1: 10(J); VAL2: 100mW
R104 R124 = R: COMPONENTTYPE: 4; INSTANCENAME: INS2263832; SIZECODESMD: 1608; VAL1: 20(F); VAL2: 100mW
TP39 TP40 = TP: COMPONENTKIND: 127; COMPONENTTYPE: 4; INSTANCENAME: INS2262622
TP43 TP44 = TP: COMPONENTKIND: 127; COMPONENTTYPE: 4; INSTANCENAME: INS2262916
U?#7 = WAKU_DEF100: COMPONENTTYPE: 2; DATE: 2026/09/14; DRAWINGNUMBER: RD256-SCHEMATIC2-01; FUNCTION: High-Side Gate Clamp; REVISION: 01; SHEETNUMBER: 3/10; SHTSAVECOUNT: 28; TITLE: E3D SiC Module Gate Driver; UPDATEDATE: 2026.9.17; UPDATETIME: 12:22:00
C116 C120 C121 C131 C136 C140 C141 C151 = C: COMPONENTTYPE: 4; INSTANCENAME: INS2265204; SIZECODESMD: 1608; VAL1: 10nF(K); VAL2: 50V
C128 C148 = C: COMPONENTTYPE: 4; INSTANCENAME: INS2265204; SIZECODESMD: 1608; VAL1: 10pF(K); VAL2: 50V
C130 C132 C150 C152 = C: COMPONENTTYPE: 4; INSTANCENAME: INS2265204; SIZECODESMD: 1608; VAL1: 1nF(K); VAL2: 50V
D40 D41 = CEZ5V6: COMPONENTTYPE: 4; INSTANCENAME: INS2265024; USERCOMPTEXT3: TOSHIBA
IC45 = TC7PZ14FU_2: COMP: TC7PZ14FU; COMPONENTTYPE: 8; CaptureCellPackProp: TC7PZ14FU_2B; INSTANCENAME: INS2264648; USERCOMPTEXT3: TOSHIBA; VAL3: TC7PZ14FU
IC50 IC63 = LTC1440IS8: COMP: LTC1440IMS8; COMPONENTTYPE: 4; INSTANCENAME: INS2264292; VAL3: LTC1440IMS8
IC51 = LM393B_1: COMP: LM393B; COMPONENTTYPE: 4; CaptureCellPackProp: LM393B_1A; INSTANCENAME: INS2264892; VAL3: LM393BIDDFR
Q21 Q27 = HN4A56JU: COMPONENTTYPE: 4; INSTANCENAME: INS2265108; USERCOMPTEXT3: TOSHIBA
Q22 Q28 = 2SC5658J: COMPONENTTYPE: 4; INSTANCENAME: INS2264212; VAL3: 2SC5658T2LR
Q23 Q29 = 2SC5658J: COMPONENTTYPE: 4; INSTANCENAME: INS2264508; VAL3: 2SC5658T2LR
Q24 Q30 = SSM3K15AFS: COMPONENTTYPE: 4; INSTANCENAME: INS2265300; USERCOMPTEXT3: TOSHIBA
Q25 Q31 = SSM3K15AFS: COMPONENTTYPE: 4; INSTANCENAME: INS2264184; USERCOMPTEXT3: TOSHIBA
R125 R150 = R: COMPONENTTYPE: 4; INSTANCENAME: INS2263832; SIZECODESMD: 1608; VAL1: 43k(F); VAL2: 100mW
R126 R127 R137 R139 R151 R152 R162 R164 = R: COMPONENTTYPE: 4; INSTANCENAME: INS2263832; SIZECODESMD: 1608; VAL1: 30k(J); VAL2: 100mW
R129 R154 = R: COMPONENTTYPE: 4; INSTANCENAME: INS2263832; SIZECODESMD: 1608; VAL1: 12k(F); VAL2: 100mW
R130 R155 = R: COMPONENTTYPE: 4; INSTANCENAME: INS2263832; SIZECODESMD: 1608; VAL1: 2.2k(F); VAL2: 100mW
R131 R156 = R: COMPONENTTYPE: 4; INSTANCENAME: INS2263832; SIZECODESMD: 1608; VAL1: 1k(F); VAL2: 100mW
R132 R157 = R: COMPONENTTYPE: 4; INSTANCENAME: INS2263832; SIZECODESMD: 1608; VAL1: 8.2k(F); VAL2: 100mW
R133 R158 = R: COMPONENTTYPE: 4; INSTANCENAME: INS2263832; SIZECODESMD: 1608; VAL1: 10k(F); VAL2: 100mW
R134 R140 R159 R165 = R: COMPONENTTYPE: 4; INSTANCENAME: INS2263832; SIZECODESMD: 1608; VAL1: 27k(F); VAL2: 100mW
R135 R160 = R: COMPONENTTYPE: 4; INSTANCENAME: INS2263832; SIZECODESMD: 1608; VAL1: 3.3k(F); VAL2: 100mW
R136 R138 R143 R161 R163 R168 R178 R179 R183 R184 = R: COMPONENTTYPE: 4; INSTANCENAME: INS2263832; SIZECODESMD: 1608; VAL1: 1k(J); VAL2: 100mW
R142 R167 = R: COMPONENTTYPE: 4; INSTANCENAME: INS2263832; SIZECODESMD: 1608; VAL1: 3k(F); VAL2: 100mW
R144 R169 = R: COMPONENTTYPE: 4; INSTANCENAME: INS2263832; SIZECODESMD: 1608; VAL1: 4.7k(J); VAL2: 100mW
R146 R171 = R: COMPONENTTYPE: 4; INSTANCENAME: INS2263832; SIZECODESMD: 1608; VAL1: 15k(F); VAL2: 100mW
R147 R172 = R: COMPONENTTYPE: 4; INSTANCENAME: INS2263832; SIZECODESMD: 1608; VAL1: 18k(F); VAL2: 100mW
R148 R173 = R: COMPONENTTYPE: 4; INSTANCENAME: INS2263832; SIZECODESMD: 1608; VAL1: 2.4M(F); VAL2: 100mW
R175 R176 R180 R181 = R: COMPONENTTYPE: 4; INSTANCENAME: INS2263832; SIZECODESMD: 1608; VAL1: 220(J); VAL2: 100mW
R177 R182 = R: COMPONENTTYPE: 4; INSTANCENAME: INS2264424; SIZECODESMD: 1608; VAL1: 0
TP46 TP48 = TP: COMPONENTKIND: 127; COMPONENTTYPE: 4; INSTANCENAME: INS2264820
U?#6 = WAKU_DEF100: COMPONENTTYPE: 2; DATE: 2026/09/14; DRAWINGNUMBER: RD256-SCHEMATIC2-01; FUNCTION: High-Side Protection; REVISION: 01; SHEETNUMBER: 4/10; SHTSAVECOUNT: 30; TITLE: E3D SiC Module Gate Driver; UPDATEDATE: 2026.9.17; UPDATETIME: 12:22:01
C35 C40 C54 C59 = C: COMPONENTTYPE: 4; INSTANCENAME: INS2266227; SIZECODESMD: 1608; VAL1: 1uF(K); VAL2: 50V
C37 C57 = C: COMPONENTTYPE: 4; INSTANCENAME: INS2266227; SIZECODESMD: 2012; VAL1: 4.7uF(K); VAL2: 50V
C38 C58 C159 C160 = C: COMPONENTTYPE: 4; INSTANCENAME: INS2266227; NOTMOUNT: NOT MOUNT; SIZECODESMD: 2012
C39 C47 C48 C56 C66 C67 = C: COMPONENTTYPE: 4; INSTANCENAME: INS2266227; SIZECODESMD: 1608; VAL1: 0.47uF(K); VAL2: 50V
IC14 IC18 = S1213B00HV5T2U7: COMPONENTTYPE: 4; INSTANCENAME: INS2266489
IC15 IC19 = TLV709: COMPONENTTYPE: 4; INSTANCENAME: INS2266385; VAL3: TLV709A01DBVR
IC17 IC21 = TCR1HF50B: COMPONENTTYPE: 4; INSTANCENAME: INS2266087; USERCOMPTEXT3: TOSHIBA
R27 R48 = R: COMPONENTTYPE: 4; INSTANCENAME: INS2266059; SIZECODESMD: 1608; VAL1: 200k(F); VAL2: 100mW
R28 R49 = R: COMPONENTTYPE: 4; INSTANCENAME: INS2266059; SIZECODESMD: 1608; VAL1: 2k(F); VAL2: 100mW
R30 R34 R51 R55 = R: COMPONENTTYPE: 4; INSTANCENAME: INS2266059; SIZECODESMD: 1608; VAL1: 1M(F); VAL2: 100mW
R31 R52 = R: COMPONENTTYPE: 4; INSTANCENAME: INS2266059; SIZECODESMD: 1608; VAL1: 4.7M(F); VAL2: 100mW
R33 R54 = R: COMPONENTTYPE: 4; INSTANCENAME: INS2266059; SIZECODESMD: 1608; VAL1: 20k(F); VAL2: 100mW
R35 R56 = R: COMPONENTTYPE: 4; INSTANCENAME: INS2266059; SIZECODESMD: 1608; VAL1: 3.3M(F); VAL2: 100mW
TP11 TP16 = TP: COMPONENTKIND: 127; COMPONENTTYPE: 4; INSTANCENAME: INS2266317
TP12 TP17 = TP: COMPONENTKIND: 127; COMPONENTTYPE: 4; INSTANCENAME: INS2266305
TP14 TP19 = TP: COMPONENTKIND: 127; COMPONENTTYPE: 4; INSTANCENAME: INS2266293
U?#5 = WAKU_DEF100: COMPONENTTYPE: 2; DATE: 2026/09/14; DRAWINGNUMBER: RD256-SCHEMATIC2-01; FUNCTION: High-Side Power Supply; REVISION: 01; SHEETNUMBER: 5/10; SHTSAVECOUNT: 21; TITLE: E3D SiC Module Gate Driver; UPDATEDATE: 2026.9.17; UPDATETIME: 11:30:53
IC56 = TC7PZ14FU_2: COMP: TC7PZ14FU; COMPONENTTYPE: 8; CaptureCellPackProp: TC7PZ14FU_2A; FUNCN: TC7PZ14FU_1; INSTANCENAME: INS2254016; USERCOMPTEXT3: TOSHIBA; VAL3: TC7PZ14FU; SAVECOUNT: 6
U?#4 = WAKU_DEF100: COMPONENTTYPE: 2; DATE: 2026/09/14; DRAWINGNUMBER: RD256-SCHEMATIC2-01; FUNCTION: Low-Side Control Logic; REVISION: 01; SHEETNUMBER: 6/10; SHTSAVECOUNT: 33; TITLE: E3D SiC Module Gate Driver; UPDATEDATE: 2026.9.17; UPDATETIME: 12:22:00
IC38 = TC7WZ08FK_1: COMPONENTTYPE: 8; CaptureCellPackProp: TC7WZ08FK_1B; FUNCN: TC7WZ08FK_2; INSTANCENAME: INS2255362; USERCOMPTEXT3: TOSHIBA
IC40 IC41 = TC7PZ14FU_2: COMP: TC7PZ14FU; COMPONENTTYPE: 8; CaptureCellPackProp: TC7PZ14FU_2A; FUNCN: TC7PZ14FU_1; INSTANCENAME: INS2255542; SAVECOUNT: 4; USERCOMPTEXT3: TOSHIBA; VAL3: TC7PZ14FU
U?#3 = WAKU_DEF100: COMPONENTTYPE: 2; DATE: 2026/09/14; DRAWINGNUMBER: RD256-SCHEMATIC2-01; FUNCTION: Low-Side Gate Drive; REVISION: 01; SHEETNUMBER: 7/10; SHTSAVECOUNT: 30; TITLE: E3D SiC Module Gate Driver; UPDATEDATE: 2026.9.17; UPDATETIME: 12:22:01
IC28 = TC7PZ14FU_2: COMP: TC7PZ14FU; COMPONENTTYPE: 8; CaptureCellPackProp: TC7PZ14FU_2B; SAVECOUNT: 6; USERCOMPTEXT3: TOSHIBA; VAL3: TC7PZ14FU
IC30 = TC75S57FU: COMPONENTTYPE: 4; INSTANCENAME: INS2262824; USERCOMPTEXT3: TOSHIBA
IC32 = TC7PZ14FU_2: COMP: TC7PZ14FU; COMPONENTTYPE: 8; CaptureCellPackProp: TC7PZ14FU_2A; FUNCN: TC7PZ14FU_1; USERCOMPTEXT3: TOSHIBA; VAL3: TC7PZ14FU; SAVECOUNT: 6
IC33 = TC7WZ00FK_2: COMPONENTTYPE: 8; CaptureCellPackProp: TC7WZ00FK_2B; SAVECOUNT: 3; USERCOMPTEXT3: TOSHIBA
U?#2 = WAKU_DEF100: COMPONENTTYPE: 2; DATE: 2026/09/14; DRAWINGNUMBER: RD256-SCHEMATIC2-01; FUNCTION: Low-Side Gate Clamp; REVISION: 01; SHEETNUMBER: 8/10; SHTSAVECOUNT: 23; TITLE: E3D SiC Module Gate Driver; UPDATEDATE: 2026.9.17; UPDATETIME: 12:22:01
IC64 = LM393B_1: COMP: LM393B; COMPONENTTYPE: 8; CaptureCellPackProp: LM393B_1A; INSTANCENAME: INS2264892; VAL3: LM393BIDDFR
U?#1 = WAKU_DEF100: COMPONENTTYPE: 2; DATE: 2026/09/14; DRAWINGNUMBER: RD256-SCHEMATIC2-01; FUNCTION: Low-Side Protection; REVISION: 01; SHEETNUMBER: 9/10; SHTSAVECOUNT: 24; TITLE: E3D SiC Module Gate Driver; UPDATEDATE: 2026.9.17; UPDATETIME: 12:22:00
U?#10 = WAKU_DEF100: COMPONENTTYPE: 2; DATE: 2026/09/14; DRAWINGNUMBER: RD256-SCHEMATIC2-01; FUNCTION: Low-Side Power Supply; REVISION: 01; SHEETNUMBER: 10/10; SHTSAVECOUNT: 18; TITLE: E3D SiC Module Gate Driver; UPDATEDATE: 2026.9.17; UPDATETIME: 11:30:54

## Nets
VIN_A: IC36.1 IC44.3 IC47.7 R136.2
VIN_B: IC40.1 IC56.3 IC59.7 R161.2
DESAT_A: C89.2 D29.2(C) D30.2(C) IC51.2 Q22.3(C) R85.1 R87.2 R177.1 TP41.1
DESAT_B: C101.2 D36.2(C) D37.2(C) IC64.2 Q28.3(C) R105.1 R107.2 R182.1 TP42.1
DESAT_N_A: IC48.4 IC49.5(2A) TP46.1
DESAT_N_B: IC60.4 IC61.5(2A) TP48.1
FAULT_2_A: CN2.9 IC53.4
FAULT_2_B: CN3.9 IC65.4
GCLP_EN_A: IC25.1 IC27.2 IC46.3
GCLP_EN_B: IC31.1 IC33.2 IC58.3
IN2_A: IC7.4 IC42.1 IC47.2
IN2_A_EN: IC42.6(2B) IC42.7 IC47.1 IC47.5
IN2_B: IC11.4 IC55.1 IC59.2
IN2_B_EN: IC55.6(2B) IC55.7 IC59.1 IC59.5
IN2_N_A: CN2.8 IC7.1 R187.2
IN2_N_B: CN3.8 IC11.1 R188.2
POR_A: IC45.4 IC46.2 IC49.1
POR_B: IC57.4 IC58.2 IC61.1
PRED_EN_A: C155.1 IC35.6 IC44.1 IC46.6 IC47.6 IC49.6(2B) IC49.7
PRED_EN_B: C158.1 IC39.6 IC56.1 IC58.6 IC59.6 IC61.6(2B) IC61.7
SIG0012: IC42.2 IC42.3(2Y)
SIG0013: IC44.4 IC46.5
SIG0022: Q16.1 Q16.2 Q16.5 Q16.6 R93.1 R97.1 R98.1
SIG0026: IC35.10 R103.1
SIG0028: IC35.4 R90.1
SIG0034: IC23.4 R72.1
SIG0039: C77.2 IC25.3 R69.2
SIG0041: Q24.1(G) R136.1
SIG0043: C130.2 IC43.1 R139.1 R143.1
SIG0044: IC48.3 IC48.6
SIG00045: R27.1 R28.2
SIG00046: IC14.4 R28.1 R33.2
SIG00047: IC15.4 R30.1 R34.2
SIG00048: R30.2 R35.1
SIG00049: R31.1 R35.2
SIG0062: IC55.5(2A) IC58.7 TP47.1
SIG0063: IC56.4 IC58.5
SIG0065: IC59.3 IC65.1
SIG0066: IC55.2 IC55.3(2Y)
SIG0067: IC61.2 IC61.3(2Y)
SIG0071: C106.2 IC39.3
SIG0072: D33.2(C) D34.1(A)
SIG0073: D33.1(A) R106.2
SIG0075: Q18.3 R110.2
SIG0076: IC38.2 IC40.3 IC40.6 R119.1
SIG0077: D34.2(C) D35.1(A)
SIG0078: R105.2 R106.1
SIG0079: IC39.10 R123.1
SIG0081: IC31.4 IC32.1
SIG0082: Q20.3 R124.2
SIG0083: R114.1 R115.1 R116.1 R120.2 R121.2 R122.2
SIG0084: IC32.6 Q12.1(G)
SIG00085: C75.2 IC24.3 R68.1 R73.2
SIG0085: IC28.6 IC33.1
SIG00086: IC24.1 R66.1 R71.2
SIG0086: IC30.1 R76.1 R81.2
SIG00087: IC24.4 R70.2
SIG00089: C78.2 IC22.1 Q10.3(C) R67.1
SIG0089: Q11.2(E) R78.2
SIG0091: C148.2 IC60.1 IC64.1 R162.1
SIG00092: IC23.1 IC27.7
SIG0092: C151.2 IC63.3(IN+) R167.1 R172.2
SIG0093: Q29.1(B) R152.1 R184.2
SIG0094: IC54.3 IC54.6 R163.2
SIG0095: IC64.7 R168.2
SIG00096: D24.1(C) Q7.1(B) Q8.3(D) R65.1
SIG0096: Q27.4(C2) R182.2
SIG00097: Q9.1(G) R72.2 R74.2 TP39.1
SIG0097: Q30.1(G) R161.1
SIG00098: Q7.2(E) R68.2
SIG0098: IC63.4(IN-) IC63.6(REF) R171.2
SIG0099: R165.1 R167.2
SIG0101: IC18.4 R49.1 R54.2
SIG0102: R52.1 R56.2
SIG0103: IC19.4 R51.1 R55.2
SIG0104: R48.1 R49.2
SIG0105: R51.2 R56.1
SIG00120: C99.2 IC37.1 R99.2
SIG00130: Q16.3 R103.2
SIG00133: Q17.1 Q17.2 Q17.5 Q17.6 R100.1 R101.1 R102.1
SIG00134: Q17.3 R104.2
SIG00135: R94.1 R95.1 R96.1 R100.2 R101.2 R102.2
SIG00136: Q15.3 R90.2
SIG00137: R85.2 R86.1
SIG00138: D26.1(A) R86.2
SIG00139: D26.2(C) D27.1(A)
SIG00140: D27.2(C) D28.1(A)
SIG00141: D28.2(C) P7.1
SIG00166: Q22.1(B) R126.1 R178.2
SIG00167: C116.1 Q21.2(B) Q21.5(C1) R131.2
SIG00168: R131.1 R133.2
SIG00170: Q23.1(B) R127.1 R179.2
SIG00171: D40.2(A) Q23.3(C) R135.2
SIG00172: C121.2 D40.1(C) IC51.6 R128.1
SIG00173: R125.1 R130.2
SIG00178: IC51.7 R143.2
SIG00180: R140.1 R142.2
SIG00181: C131.2 IC50.3(IN+) R142.1 R147.2
SIG00182: IC50.4(IN-) IC50.6(REF) R146.2
SIG00183: IC50.5(HYST) R146.1 R148.2
SIG00185: IC50.8(OUT) R144.2
SIG00186: C132.2 IC45.1 R144.1
SIG00191: IC43.3 IC43.6 R138.2
SIG00193: IC45.3 IC45.6
SIG00210: C94.2 IC35.3
SIG00211: IC34.7 IC35.8 TP32.1
SIG00213: Q15.4 R88.1 R91.1 R92.1
SIG00214: IC34.6 IC36.4
SIG00310: IC26.6 Q8.1(G)
SIG00311: IC25.4 IC26.1
SIG00312: IC22.6 IC27.1
SIG00313: IC25.6 R69.1
SIG00710: IC38.5 IC41.3 IC41.6
SIG00711: IC38.3 IC39.7 TP35.1
SIG00712: IC38.7 IC39.8 TP37.1
SIG00713: IC39.4 R110.1
SIG00714: Q19.1 Q19.2 Q19.5 Q19.6 R113.1 R117.1 R118.1
SIG00716: C111.2 IC41.1 R119.2
SIG00717: IC38.6 IC40.4
SIG00718: Q19.3 R123.2
SIG00719: IC38.1 IC41.4
SIG00720: Q18.4 R108.1 R111.1 R112.1
SIG00810: Q20.1 Q20.2 Q20.5 Q20.6 R120.1 R121.1 R122.1
SIG00811: IC29.4 R82.1
SIG00812: IC29.1 IC33.7
SIG00813: Q13.1(G) R82.2 R84.2 TP40.1
SIG00814: IC30.4 R80.2
SIG00815: C86.2 IC30.3 R78.1 R83.2
SIG00816: D25.1(C) Q11.1(B) Q12.3(D) R75.1
SIG00817: C88.2 IC28.1 Q14.3(C) R77.1
SIG00818: C87.2 IC31.3 R79.2
SIG00819: IC31.6 R79.1
SIG00910: Q28.1(B) R151.1 R183.2
SIG00911: Q27.3(E2) R180.1
SIG00912: IC63.5(HYST) R171.1 R173.2
SIG00913: D41.2(A) Q29.3(C) R160.2
SIG00914: IC63.8(OUT) R169.2
SIG00915: Q31.1(G) R163.1
SIG00916: R156.1 R158.2
SIG00917: C136.1 Q27.2(B) Q27.5(C1) R156.2
SIG00918: R150.1 R155.2
SIG00919: IC64.5 R155.1 R159.2
SIG00920: C152.2 IC57.1 R169.1
SIG00921: IC57.3 IC57.6
SIG00922: Q30.3(D) R183.1
SIG00923: C141.2 D41.1(C) IC64.6 R153.1
SIG00924: C140.2 IC64.3 R154.1 R157.2
SIG00925: IC60.3 IC60.6
SIG00926: C150.2 IC54.1 R164.1 R168.1
SIG00927: Q31.3(D) R184.1
SIG00928: Q27.1(E1) R181.1
STO_VMOS_A: IC44.6 R104.1 TP43.1
STO_VMOS_B: IC56.6 R124.1 TP44.1
UVLO_N_A: IC43.4 IC46.1
UVLO_N_B: IC54.4 IC58.1
V_0_VE_A: C35.1 C37.1 C38.1 C47.2 C89.1 C90.1 C91.1 C92.2 C97.2 C98.2 C120.1 C121.1 C153.1 C154.1 C159.1 CN2.3 CN2.4 D29.1(A) D30.1(A) D35.2(C) IC14.3 IC17.1 IC17.3 P5.1 Q22.2(E) Q23.2(E) R33.1 R87.1 R89.2 R132.1 R133.1 R134.1 R135.1
V_0_VE_B: C54.1 C57.1 C58.1 C66.2 C101.1 C102.1 C103.1 C104.2 C109.2 C110.2 C140.1 C141.1 C156.1 C157.1 C160.1 CN3.3 CN3.4 D36.1(A) D37.1(A) IC18.3 IC21.1 IC21.3 P12.1 Q28.2(E) Q29.2(E) R54.1 R107.1 R109.2 R157.1 R158.1 R159.1 R160.1
VGATE_A: C92.1 C94.1 D31.1(A) D32.2(C) IC35.5 P4.1 Q7.3(C) Q9.3(D) R65.2 R88.2 R89.1 R91.2 R92.2 R93.2 R94.2 R95.2 R96.2 R97.2 R98.2
VGATE_B: C104.1 C106.1 D38.1(A) D39.2(C) IC39.5 P11.1 Q11.3(C) Q13.3(D) R75.2 R108.2 R109.1 R111.2 R112.2 R113.2 R114.2 R115.2 R116.2 R117.2 R118.2
VN_1_A: C24.1 C48.2 C69.2 C70.2 C71.2 C72.2 C73.2 C74.2 C76.2 C93.2 C96.2 C100.2 C113.2 C114.1 C115.1 C117.2 C118.2 C119.1 C122.1 C123.2 C124.1 C126.2 CN2.7 IC7.5 IC17.5 IC22.5 IC23.5 IC24.5 IC25.5 IC26.5 IC27.8 IC34.8 IC36.5 IC37.5 IC42.8 IC43.5 IC44.5 IC45.5 IC46.8 IC47.8 IC48.5 IC49.8 IC50.7(V+) IC53.5 R66.2 R67.2 R137.2 R139.2 R140.2 TP14.1
VN_1_B: C28.1 C67.2 C79.2 C80.2 C81.2 C82.2 C83.2 C84.2 C85.2 C105.2 C108.2 C112.2 C133.2 C134.1 C135.1 C137.2 C138.2 C139.1 C142.1 C143.2 C144.1 C146.2 CN3.7 IC11.5 IC21.5 IC28.5 IC29.5 IC30.5 IC31.5 IC32.5 IC33.8 IC38.8 IC40.5 IC41.5 IC54.5 IC55.8 IC56.5 IC57.5 IC58.8 IC59.8 IC60.5 IC61.8 IC63.7(V+) IC65.5 R76.2 R77.2 R162.2 R164.2 R165.2 TP19.1
VN_6_VEE_A: C24.2 C39.1 C40.1 C47.1 C48.1 C69.1 C70.1 C71.1 C72.1 C73.1 C74.1 C75.1 C76.1 C77.1 C78.1 C93.1 C95.1 C96.1 C97.1 C98.1 C99.1 C100.1 C113.1 C114.2 C115.2 C117.1 C118.1 C119.2 C122.2 C123.1 C124.2 C126.1 C127.1 C128.1 C130.1 C131.1 C132.1 C155.2 CN2.5 CN2.6 D24.2(A) D32.1(A) IC7.2 IC15.2 IC17.2 IC22.2 IC22.3 IC23.2 IC24.2 IC25.2 IC26.2 IC26.3 IC27.4 IC27.5(2A) IC27.6(2B) IC34.4 IC35.9 IC35.11 IC36.2 IC37.2 IC42.4 IC43.2 IC44.2 IC45.2 IC46.4 IC47.4 IC48.2 IC49.4 IC50.1(GND) IC50.2(V-) IC51.4 IC53.2 Q8.2(S) Q9.2(S) Q10.2(E) Q16.4 Q17.4 Q24.2(S) Q25.2(S) R34.1 R71.1 R73.1 R74.1 R147.1 R148.1 R187.1
VN_6_VEE_B: C28.2 C56.1 C59.1 C66.1 C67.1 C79.1 C80.1 C81.1 C82.1 C83.1 C84.1 C85.1 C86.1 C87.1 C88.1 C105.1 C107.1 C108.1 C109.1 C110.1 C111.1 C112.1 C133.1 C134.2 C135.2 C137.1 C138.1 C139.2 C142.2 C143.1 C144.2 C146.1 C147.1 C148.1 C150.1 C151.1 C152.1 C158.2 CN3.5 CN3.6 D25.2(A) D39.1(A) IC11.2 IC19.2 IC21.2 IC28.2 IC28.3 IC29.2 IC30.2 IC31.2 IC32.2 IC32.3 IC33.4 IC33.5(2A) IC33.6(2B) IC38.4 IC39.9 IC39.11 IC40.2 IC41.2 IC54.2 IC55.4 IC56.2 IC57.2 IC58.4 IC59.4 IC60.2 IC61.4 IC63.1(GND) IC63.2(V-) IC64.4 IC65.2 Q12.2(S) Q13.2(S) Q14.2(E) Q19.4 Q20.4 Q30.2(S) Q31.2(S) R55.1 R81.1 R83.1 R84.1 R172.1 R173.1 R188.1
VP_6_A: C40.2 C95.2 IC15.5 IC35.1 R31.2 TP12.1
VP_6_B: C59.2 C107.2 IC19.5 IC39.1 R52.2 TP17.1
VP_20_A: C37.2 C38.2 C39.2 C90.2 C91.2 C116.2 C127.2 C153.2 C154.2 D31.2(C) IC14.5 IC15.1 IC51.8 Q15.1 Q15.2 Q15.5 Q15.6 R27.2 R125.2 R126.2 R127.2 R128.2 R129.2 R175.2 R176.2 TP11.1
VP_20_B: C56.2 C57.2 C58.2 C102.2 C103.2 C136.2 C147.2 C156.2 C157.2 D38.2(C) IC18.5 IC19.1 IC64.8 Q18.1 Q18.2 Q18.5 Q18.6 R48.2 R150.2 R151.2 R152.2 R153.2 R154.2 R180.2 R181.2 TP16.1
VP_24_A: C35.2 C159.2 CN2.1 CN2.2 IC14.1 IC14.2
VP_24_B: C54.2 C160.2 CN3.1 CN3.2 IC18.1 IC18.2
N04250: Q10.1(B) R70.1
N11148: Q14.1(B) R80.1
N85407: IC34.3 IC35.7 TP30.1
N855881: C120.2 IC51.3 R129.1 R132.2
N855931: IC51.5 R130.1 R134.2
N1924743: Q21.1(E1) R176.1
N1924835: Q21.3(E2) R175.1
N1939063: C128.2 IC48.1 IC51.1 R137.1
N1941594: Q24.3(D) R178.1
N1941665: Q25.3(D) R179.1
N1966980: Q21.4(C2) R177.2
N2078081: IC42.5(2A) IC46.7 TP45.1
N2078630: IC49.2 IC49.3(2Y)
N2080336: IC47.3 IC53.1
N2111970: IC34.5 IC37.3 IC37.6
N2111992: IC34.2 IC36.3 IC36.6 R99.1
N2112212: IC34.1 IC37.4
N22641981: Q25.1(G) R138.1

Not connected (* = marked no-connect by the designer): IC7 3; IC11 3; IC15 3; IC17 4; IC19 3; IC21 4; IC22 4; IC23 3; IC26 4; IC27 3(2Y); IC28 4; IC29 3; IC32 4; IC33 3(2Y); IC35 2; IC39 2; IC53 3; IC65 3

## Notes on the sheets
sheet 2
- 1/2
- 2/2
- 1/2
- 1/2
- 2/2
- 1/2
- 2/2
- 2/2
sheet 3
- A/2
- 1/2
- 1/2
- 1/2
- 2/2
- 2/2
- 2/2
- 2/2
sheet 4
- 2/2
- 2/2
- x3
- 1/2
- 1/2
- `1.70mm
     TH
- x3
- 1/2
- 2/2
- `1.70mm
     TH
sheet 5
- RCN3 is connected to CN3 of RD256-SCHEMATIC1
- 1/2
- 2/2
- 2/2
- 1/2
- 2/2
- 2/2
- 1/2
- 2/2
- 1/2
- 1/2
sheet 7
- 1/2
- 2/2
- 1/2
- 1/2
- 2/2
- 1/2
- 2/2
- 2/2
sheet 8
- 1/2
- 1/2
- 1/2
- 2/2
- 1/2
- 2/2
- 2/2
- 2/2
sheet 9
- `1.70mm
     TH
- 2/2
- 2/2
- x3
- 1/2
- 1/2
- 2/2
- `1.70mm
     TH
- x3
- 1/2
- `1.70mm
     TH
sheet 10
- RCN2 is connected to CN2 of RD256-SCHEMATIC1
- 1/2
- 2/2
- 2/2
- 1/2
- 2/2
- 2/2
- 1/2
- 2/2
- 1/2
- 1/2
